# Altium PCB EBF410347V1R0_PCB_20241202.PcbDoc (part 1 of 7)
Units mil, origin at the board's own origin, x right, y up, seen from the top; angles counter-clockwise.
Board outline 5098.43 x 3464.57 mil, 6 copper layers (TOP, GND02, ART03, ART04, PWR05, BOTTOM), stack 47.2 mil thick; 566 components, 452 nets, 1905 pads, 1432 vias.
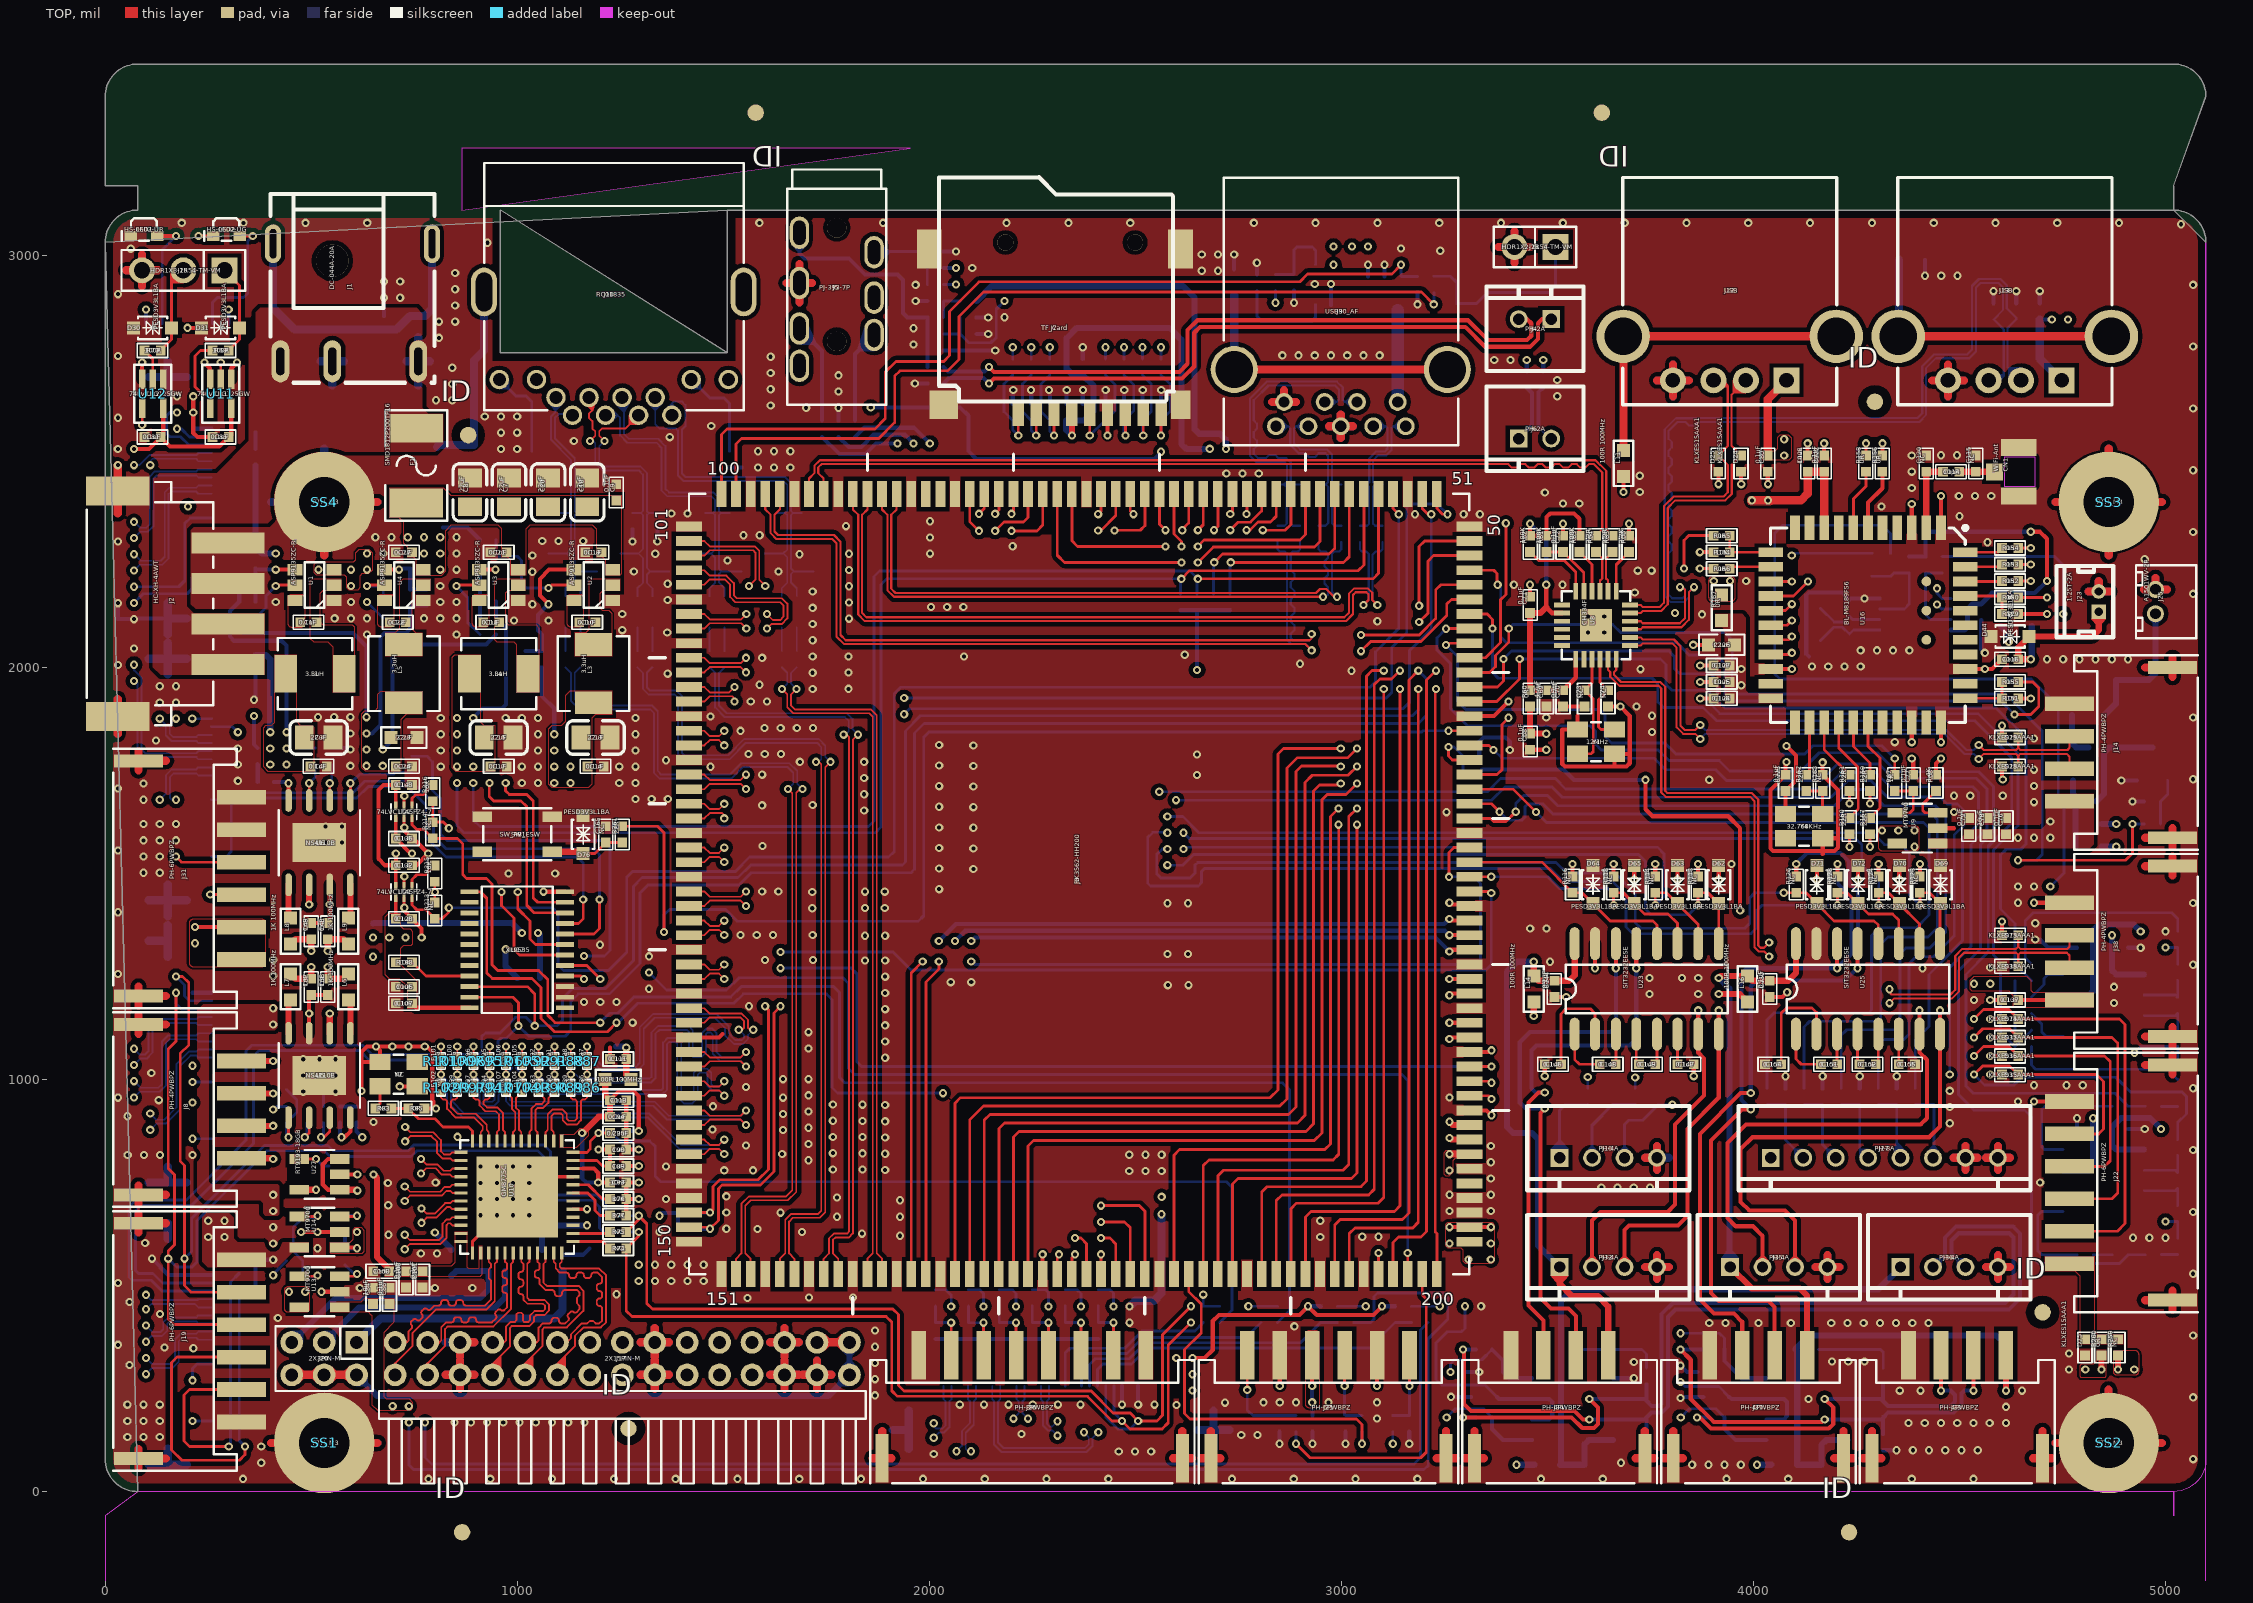
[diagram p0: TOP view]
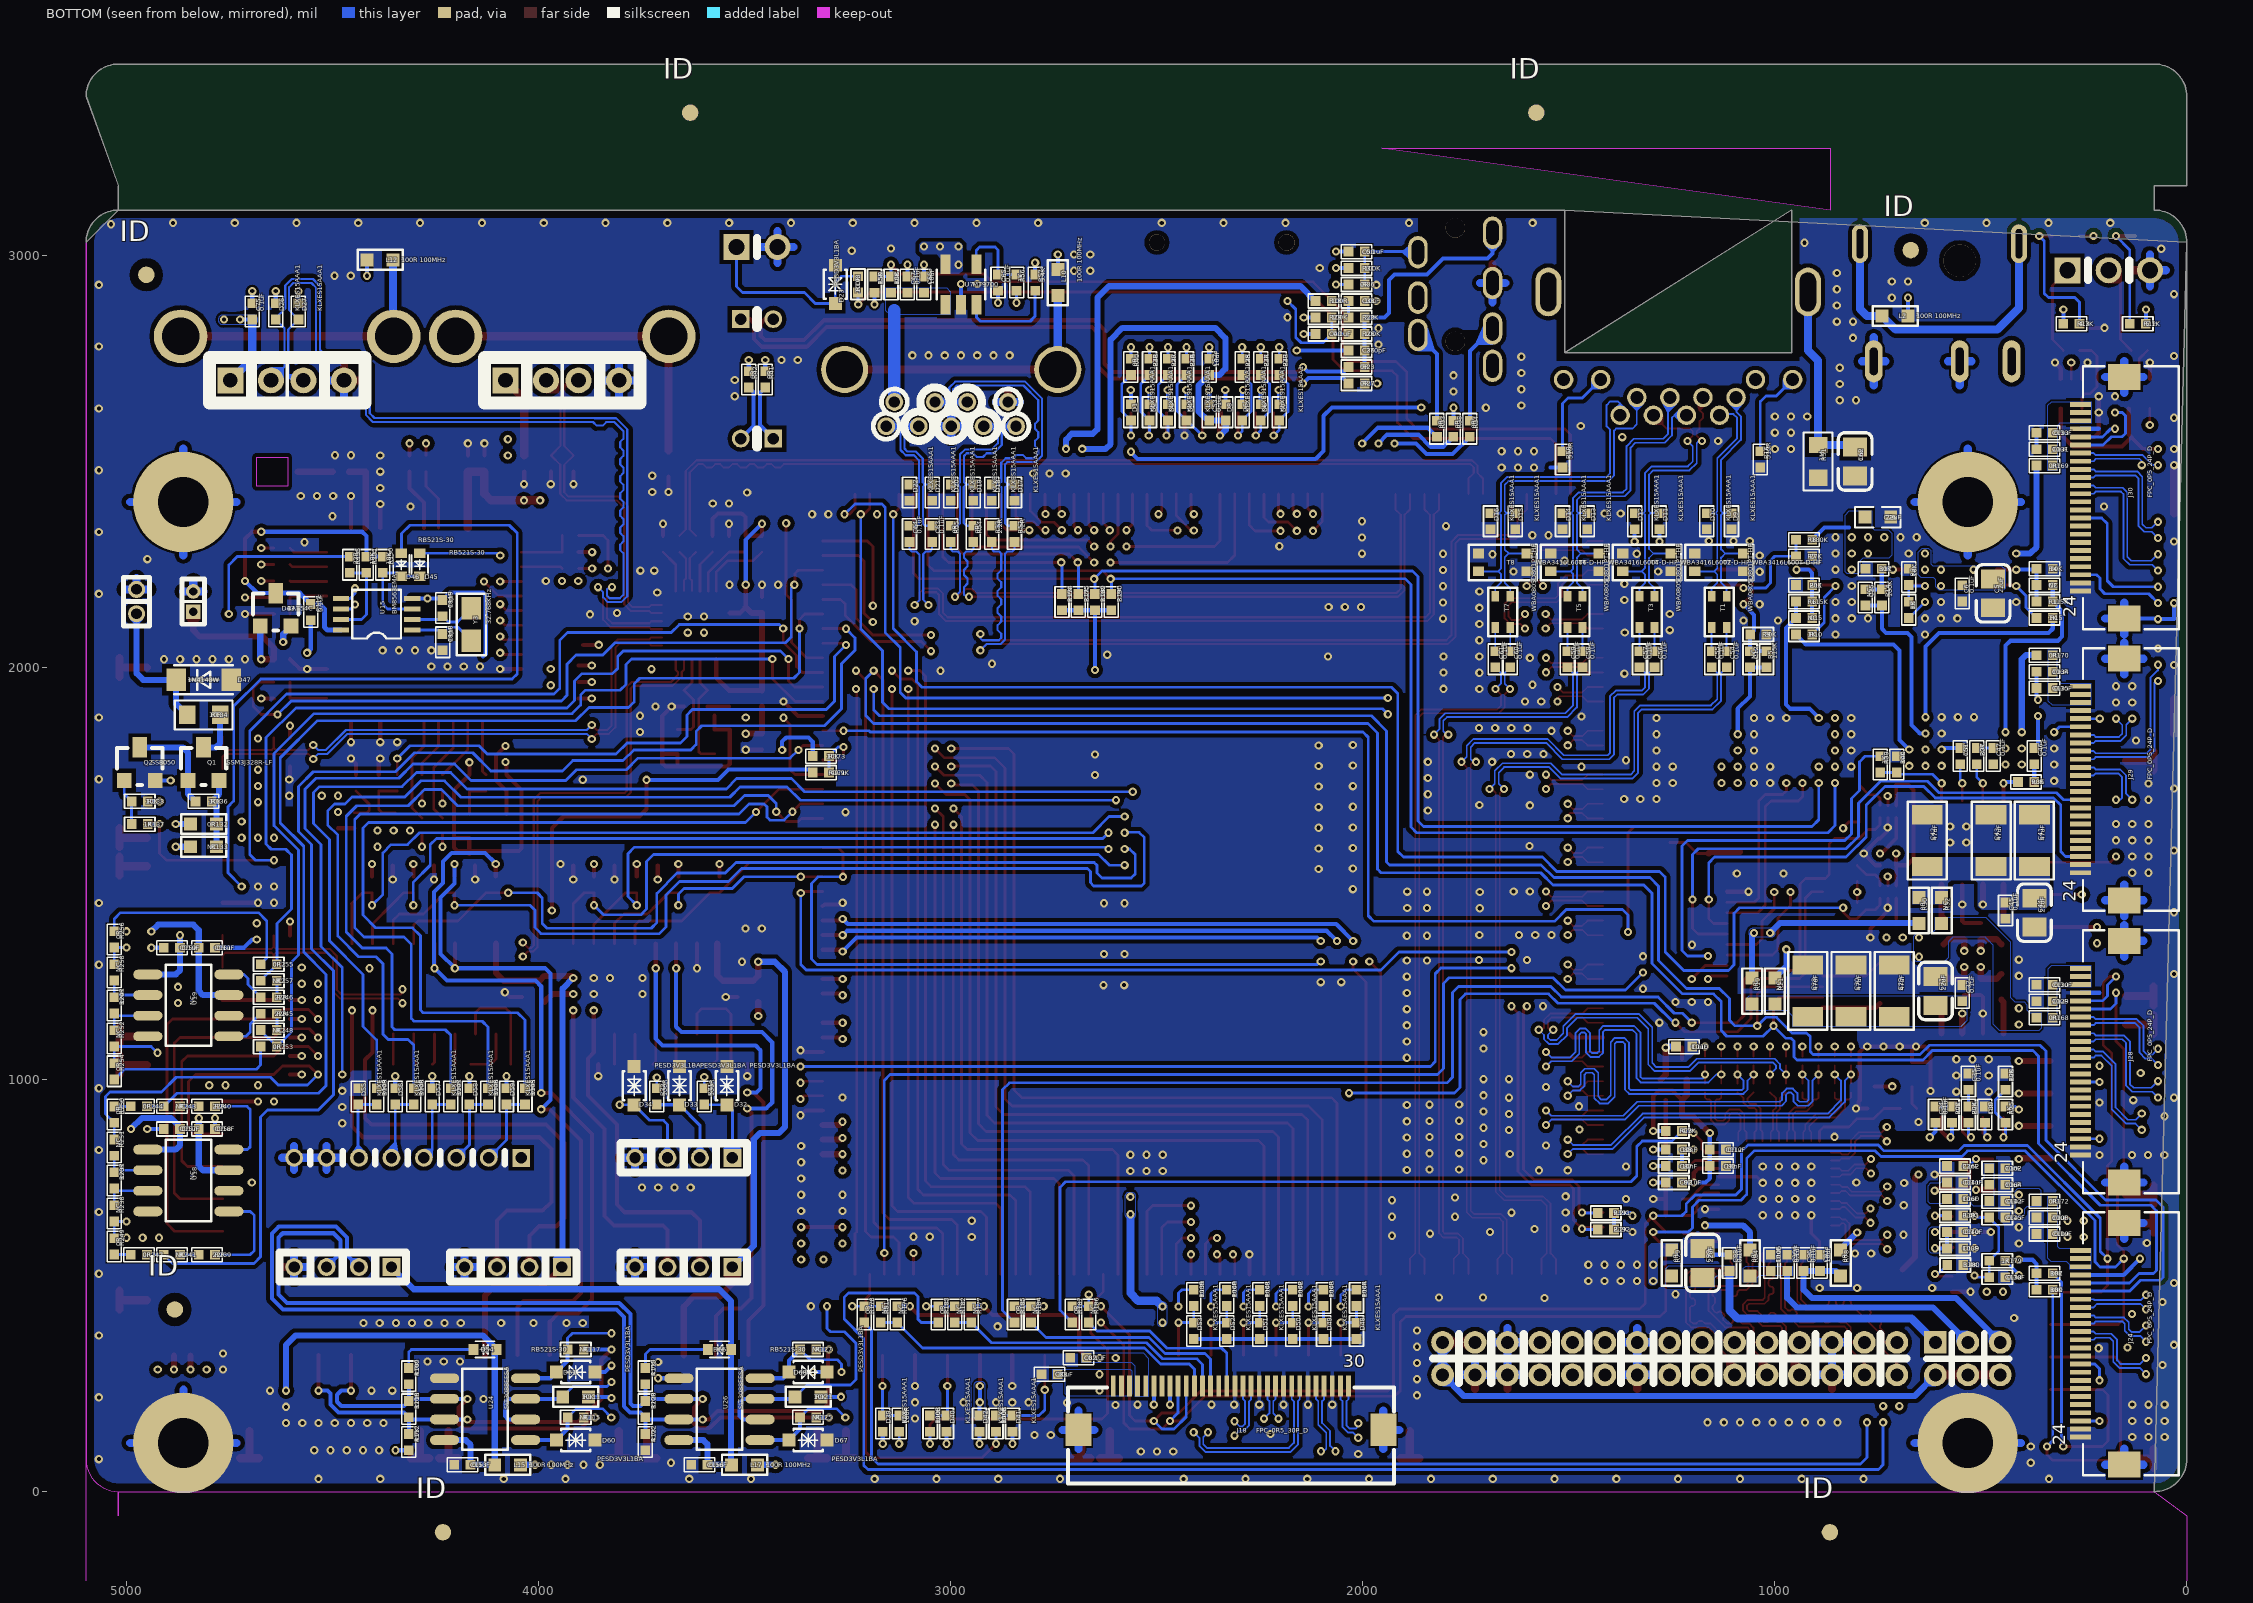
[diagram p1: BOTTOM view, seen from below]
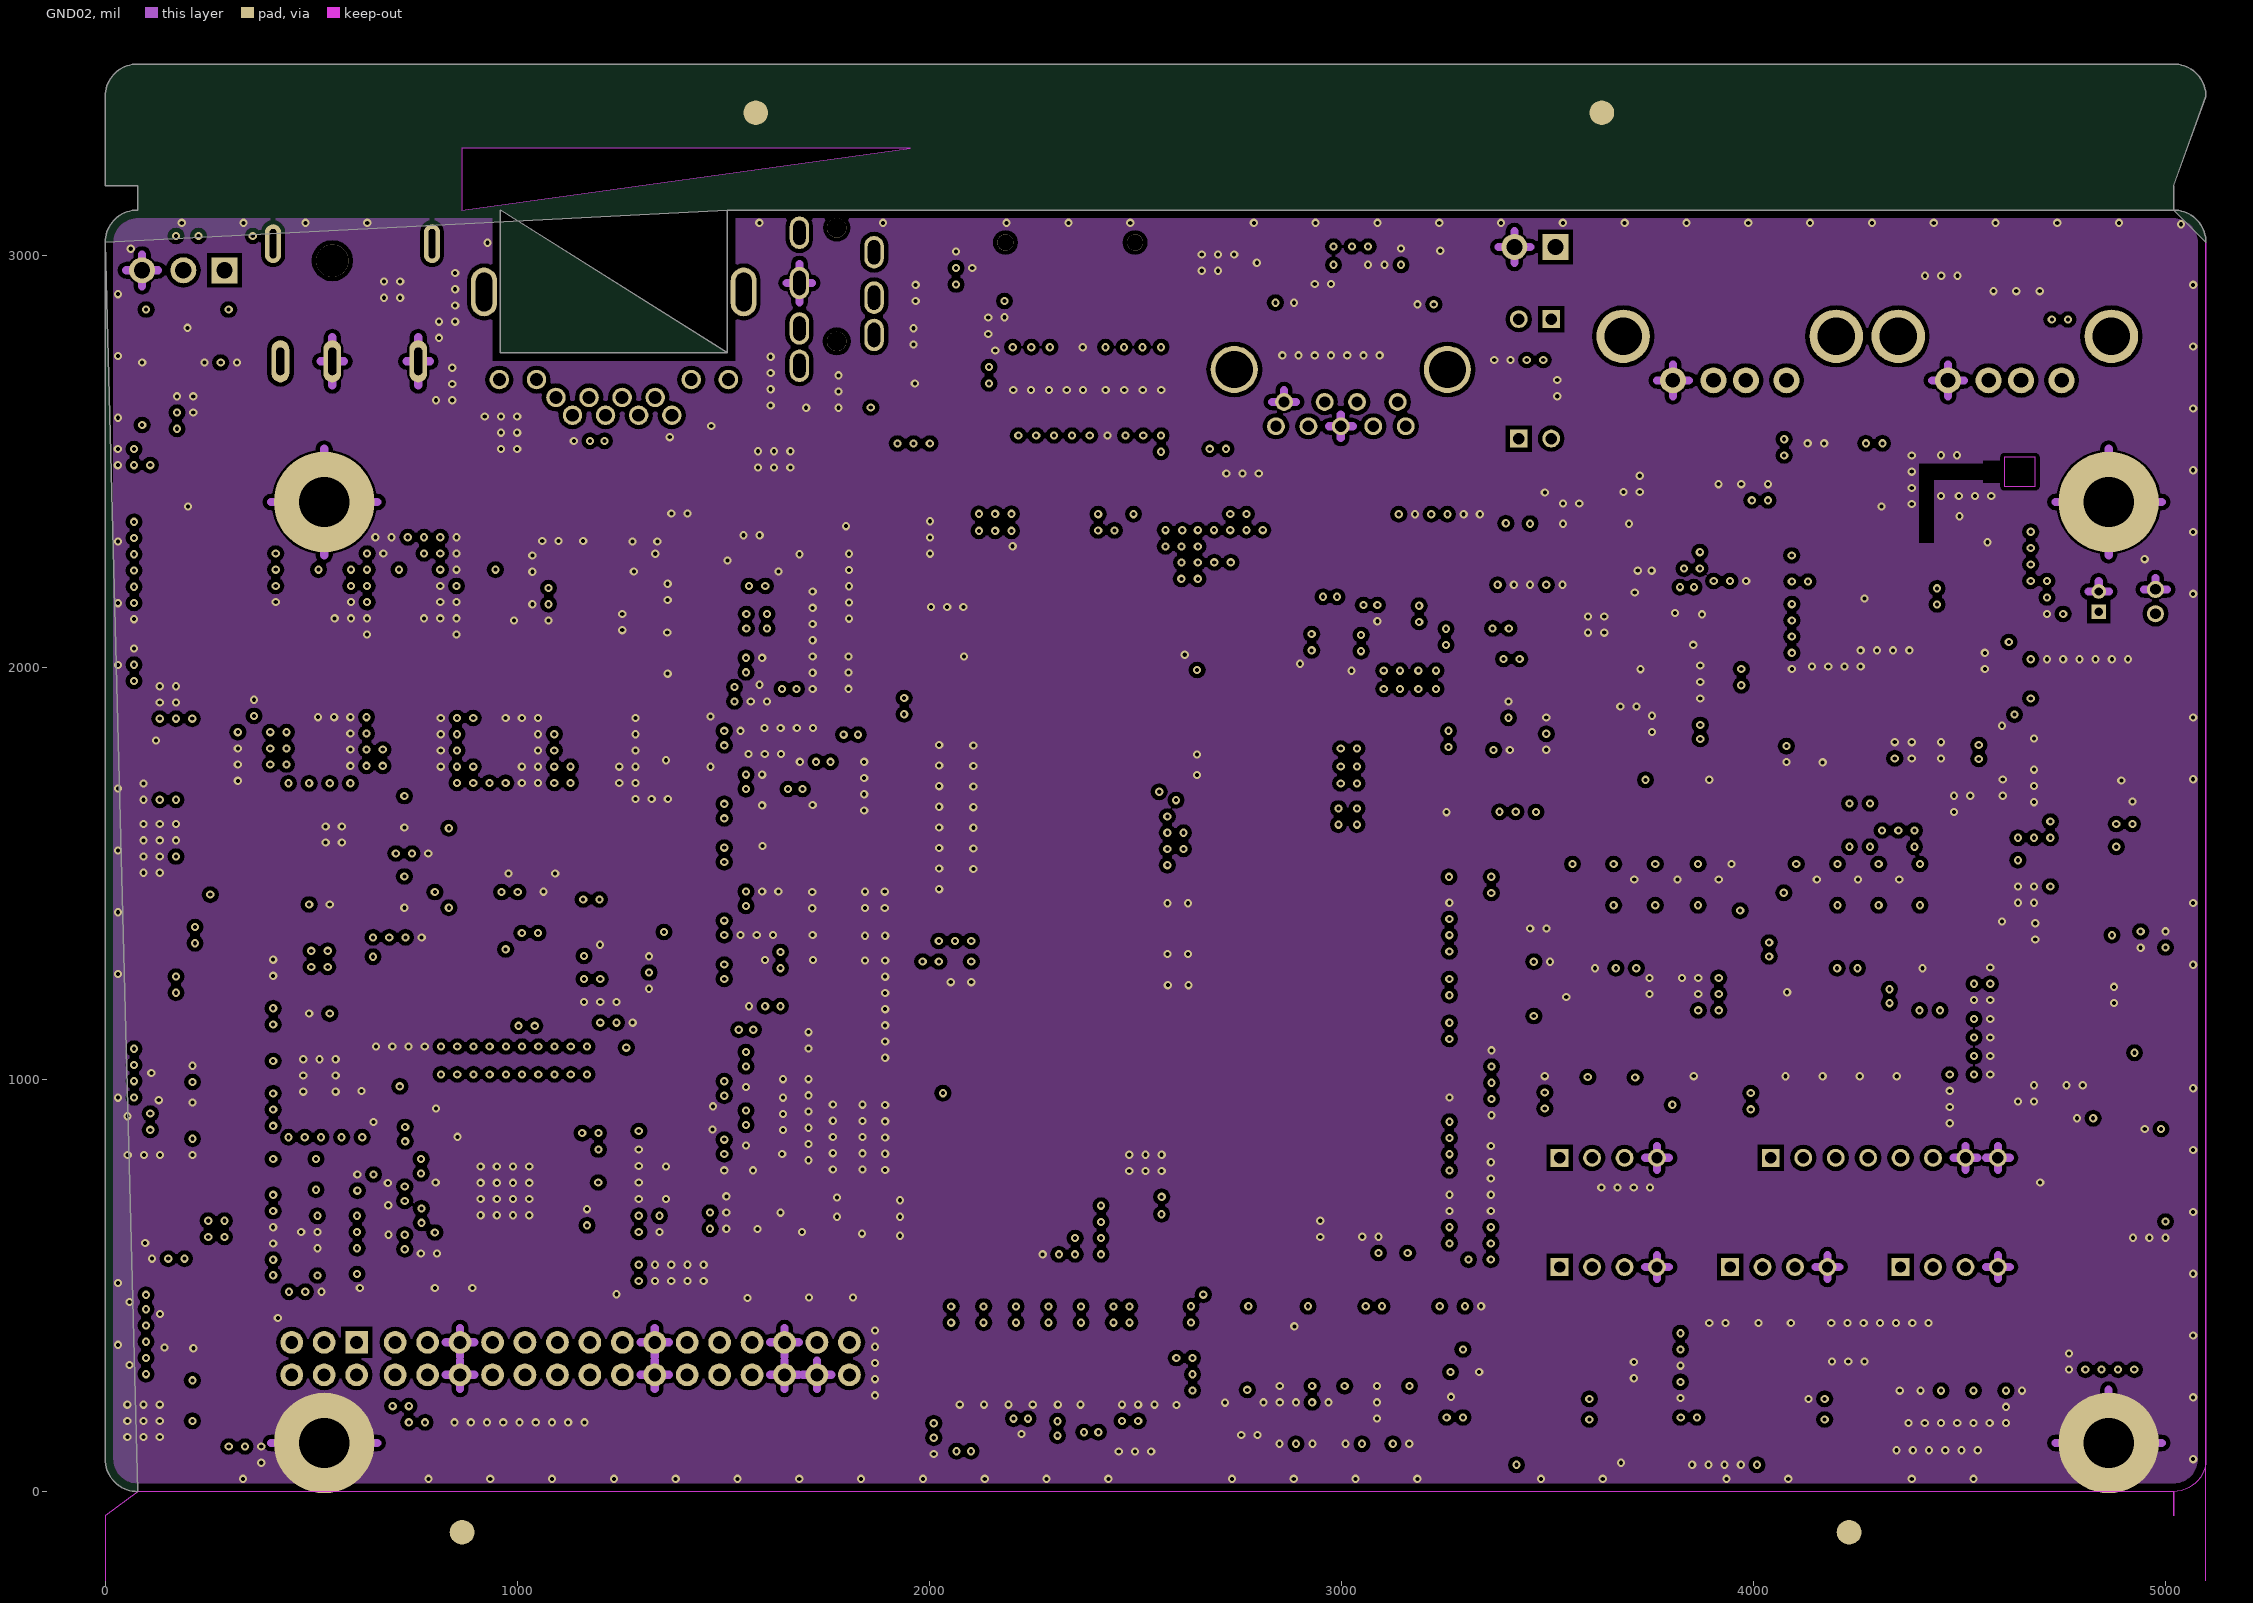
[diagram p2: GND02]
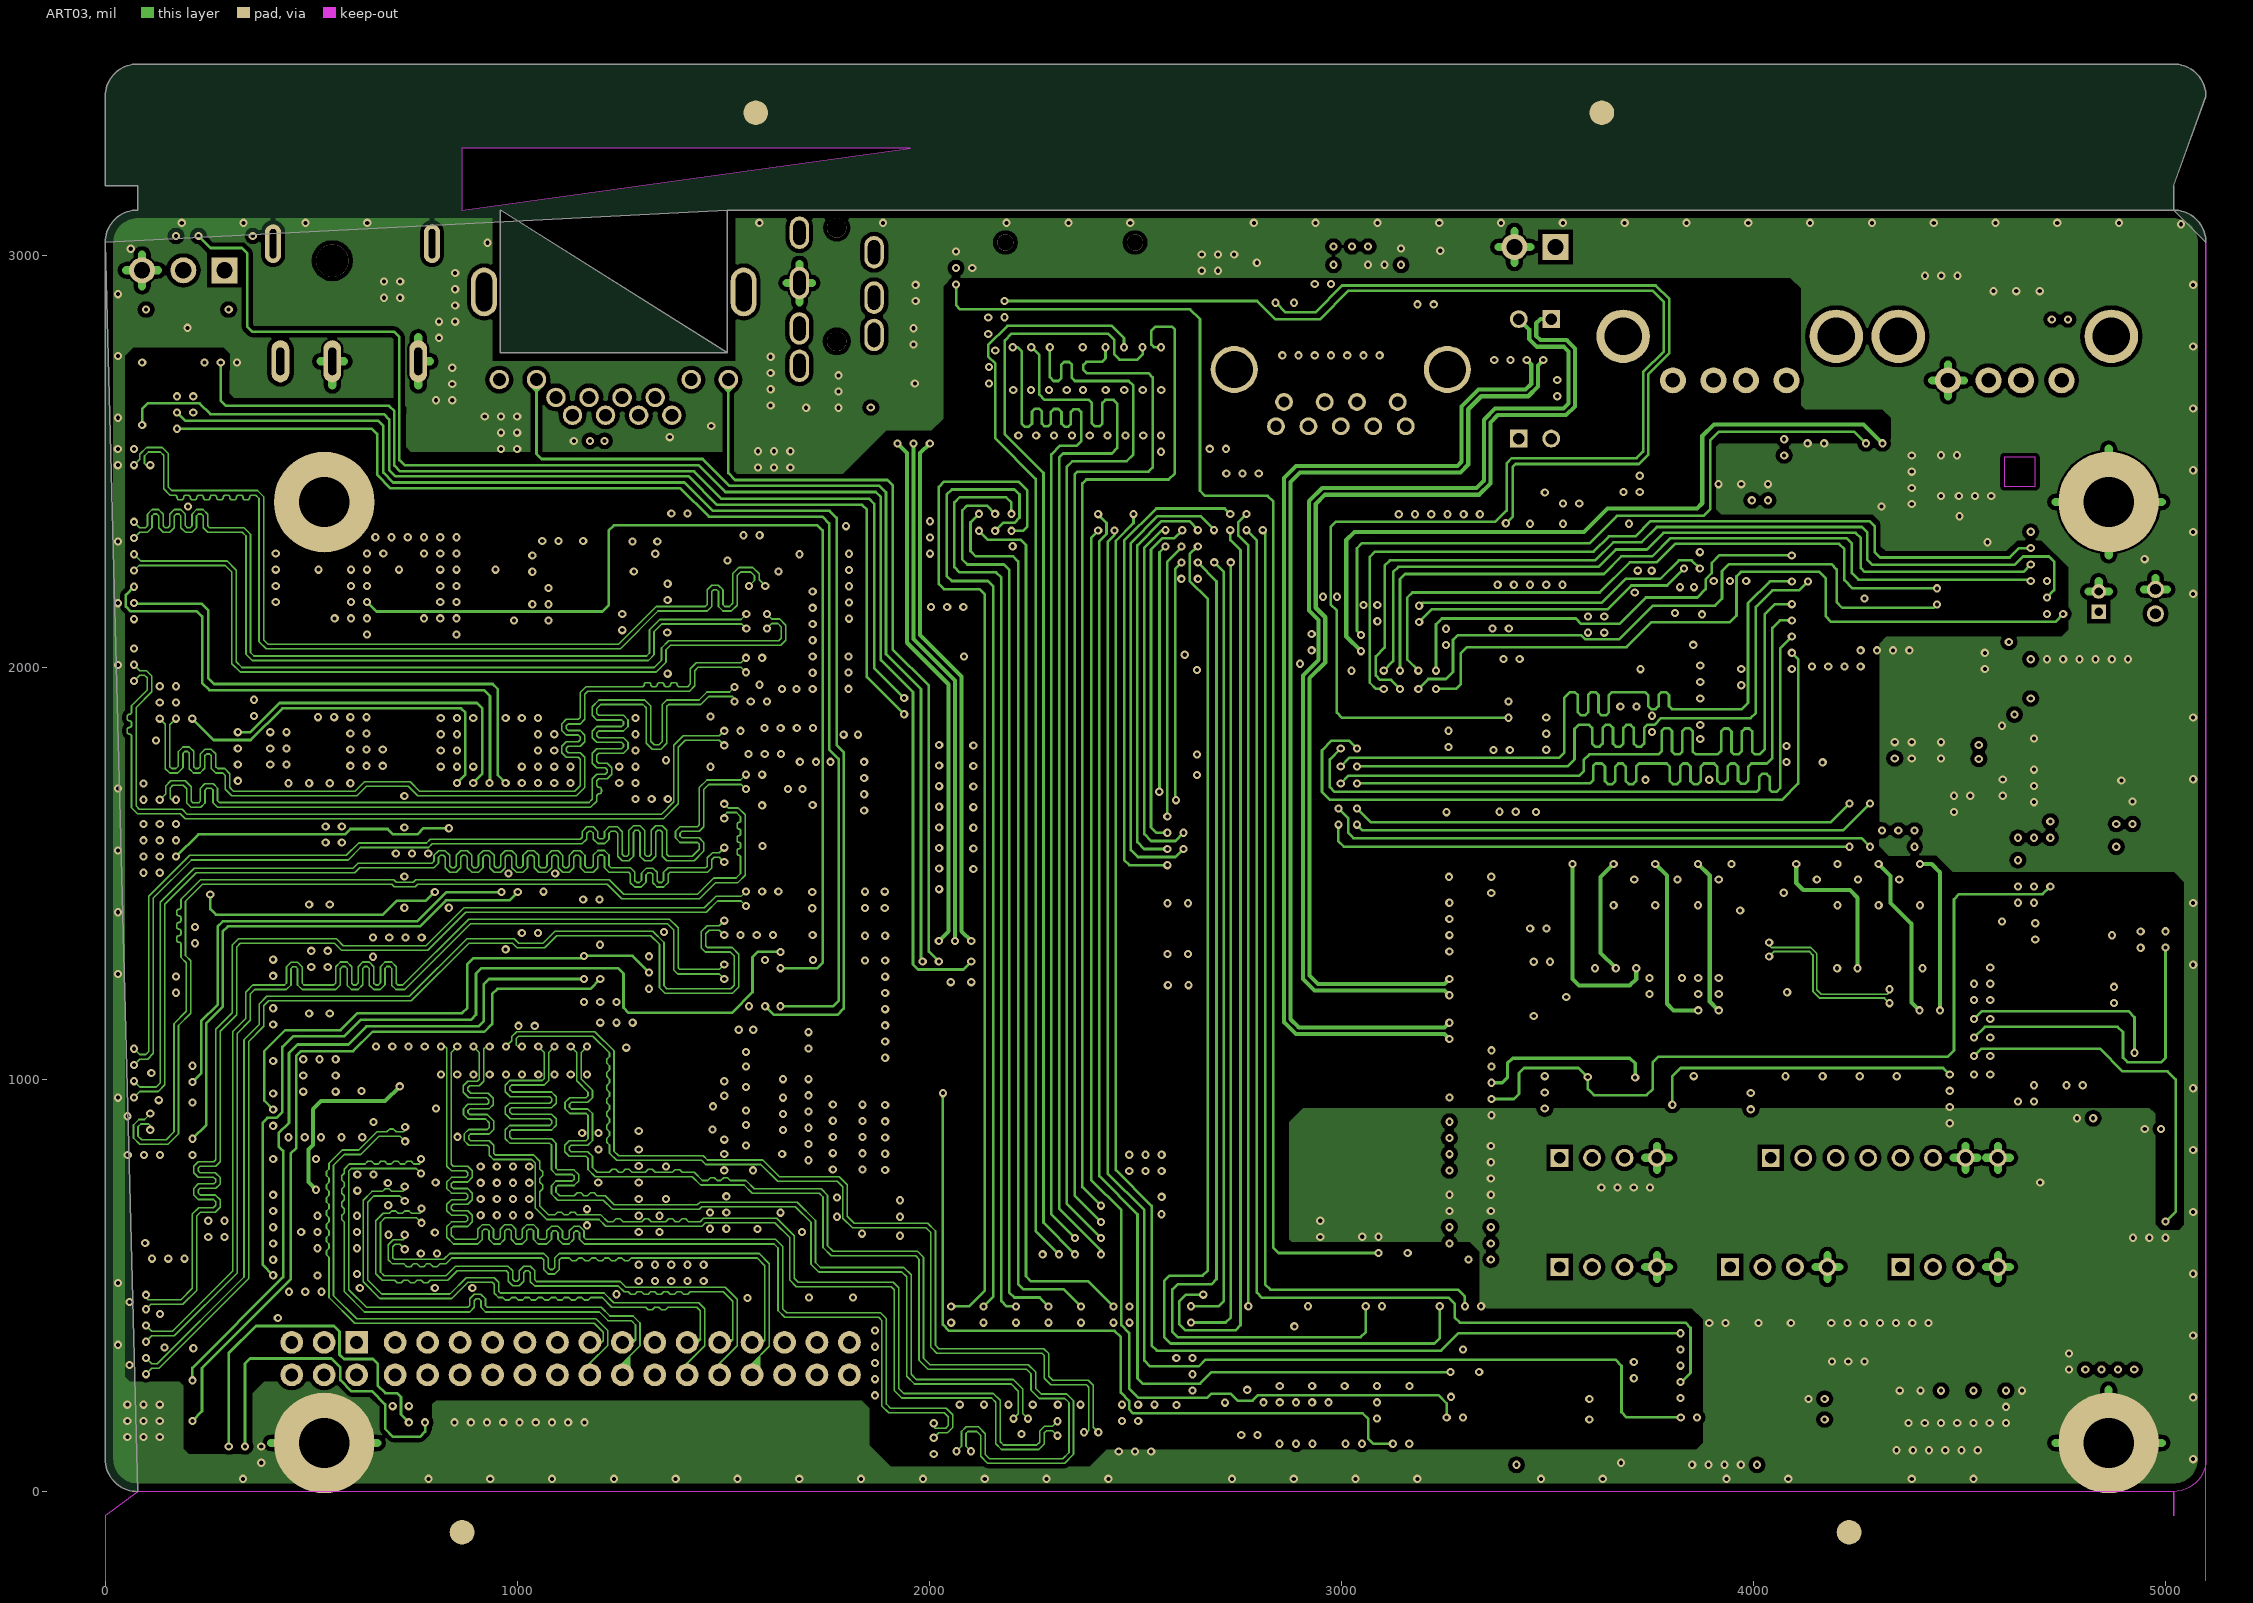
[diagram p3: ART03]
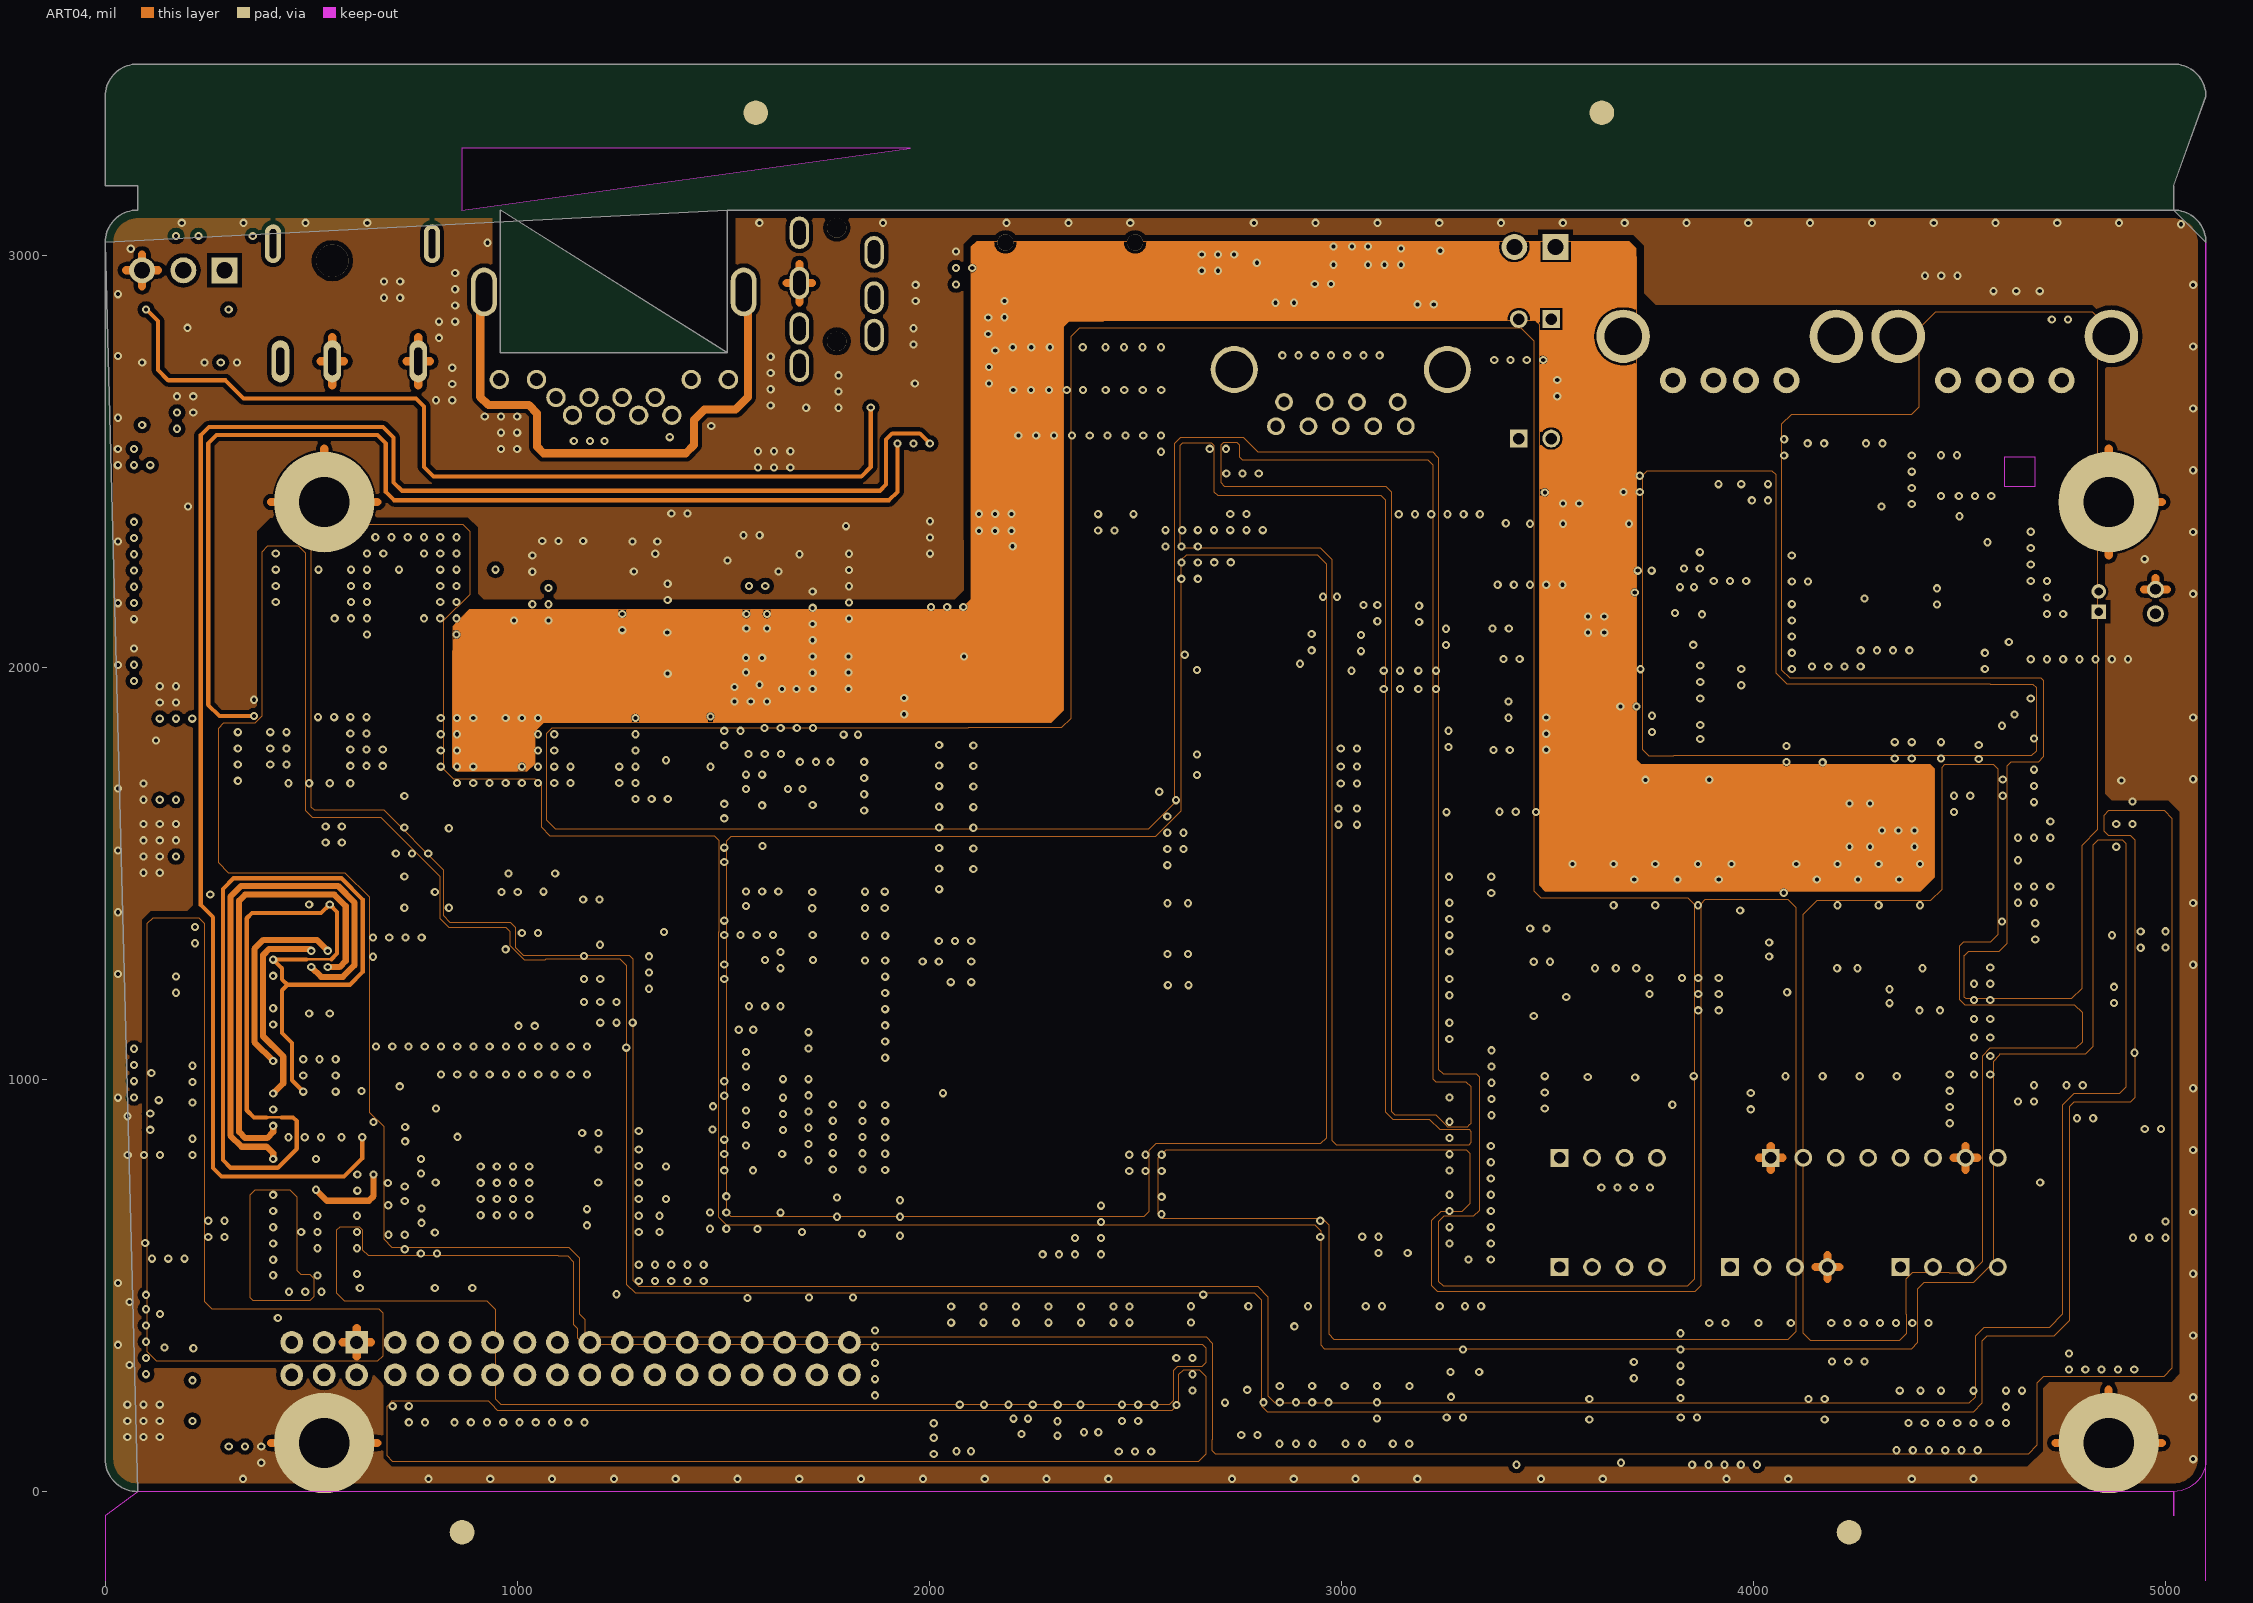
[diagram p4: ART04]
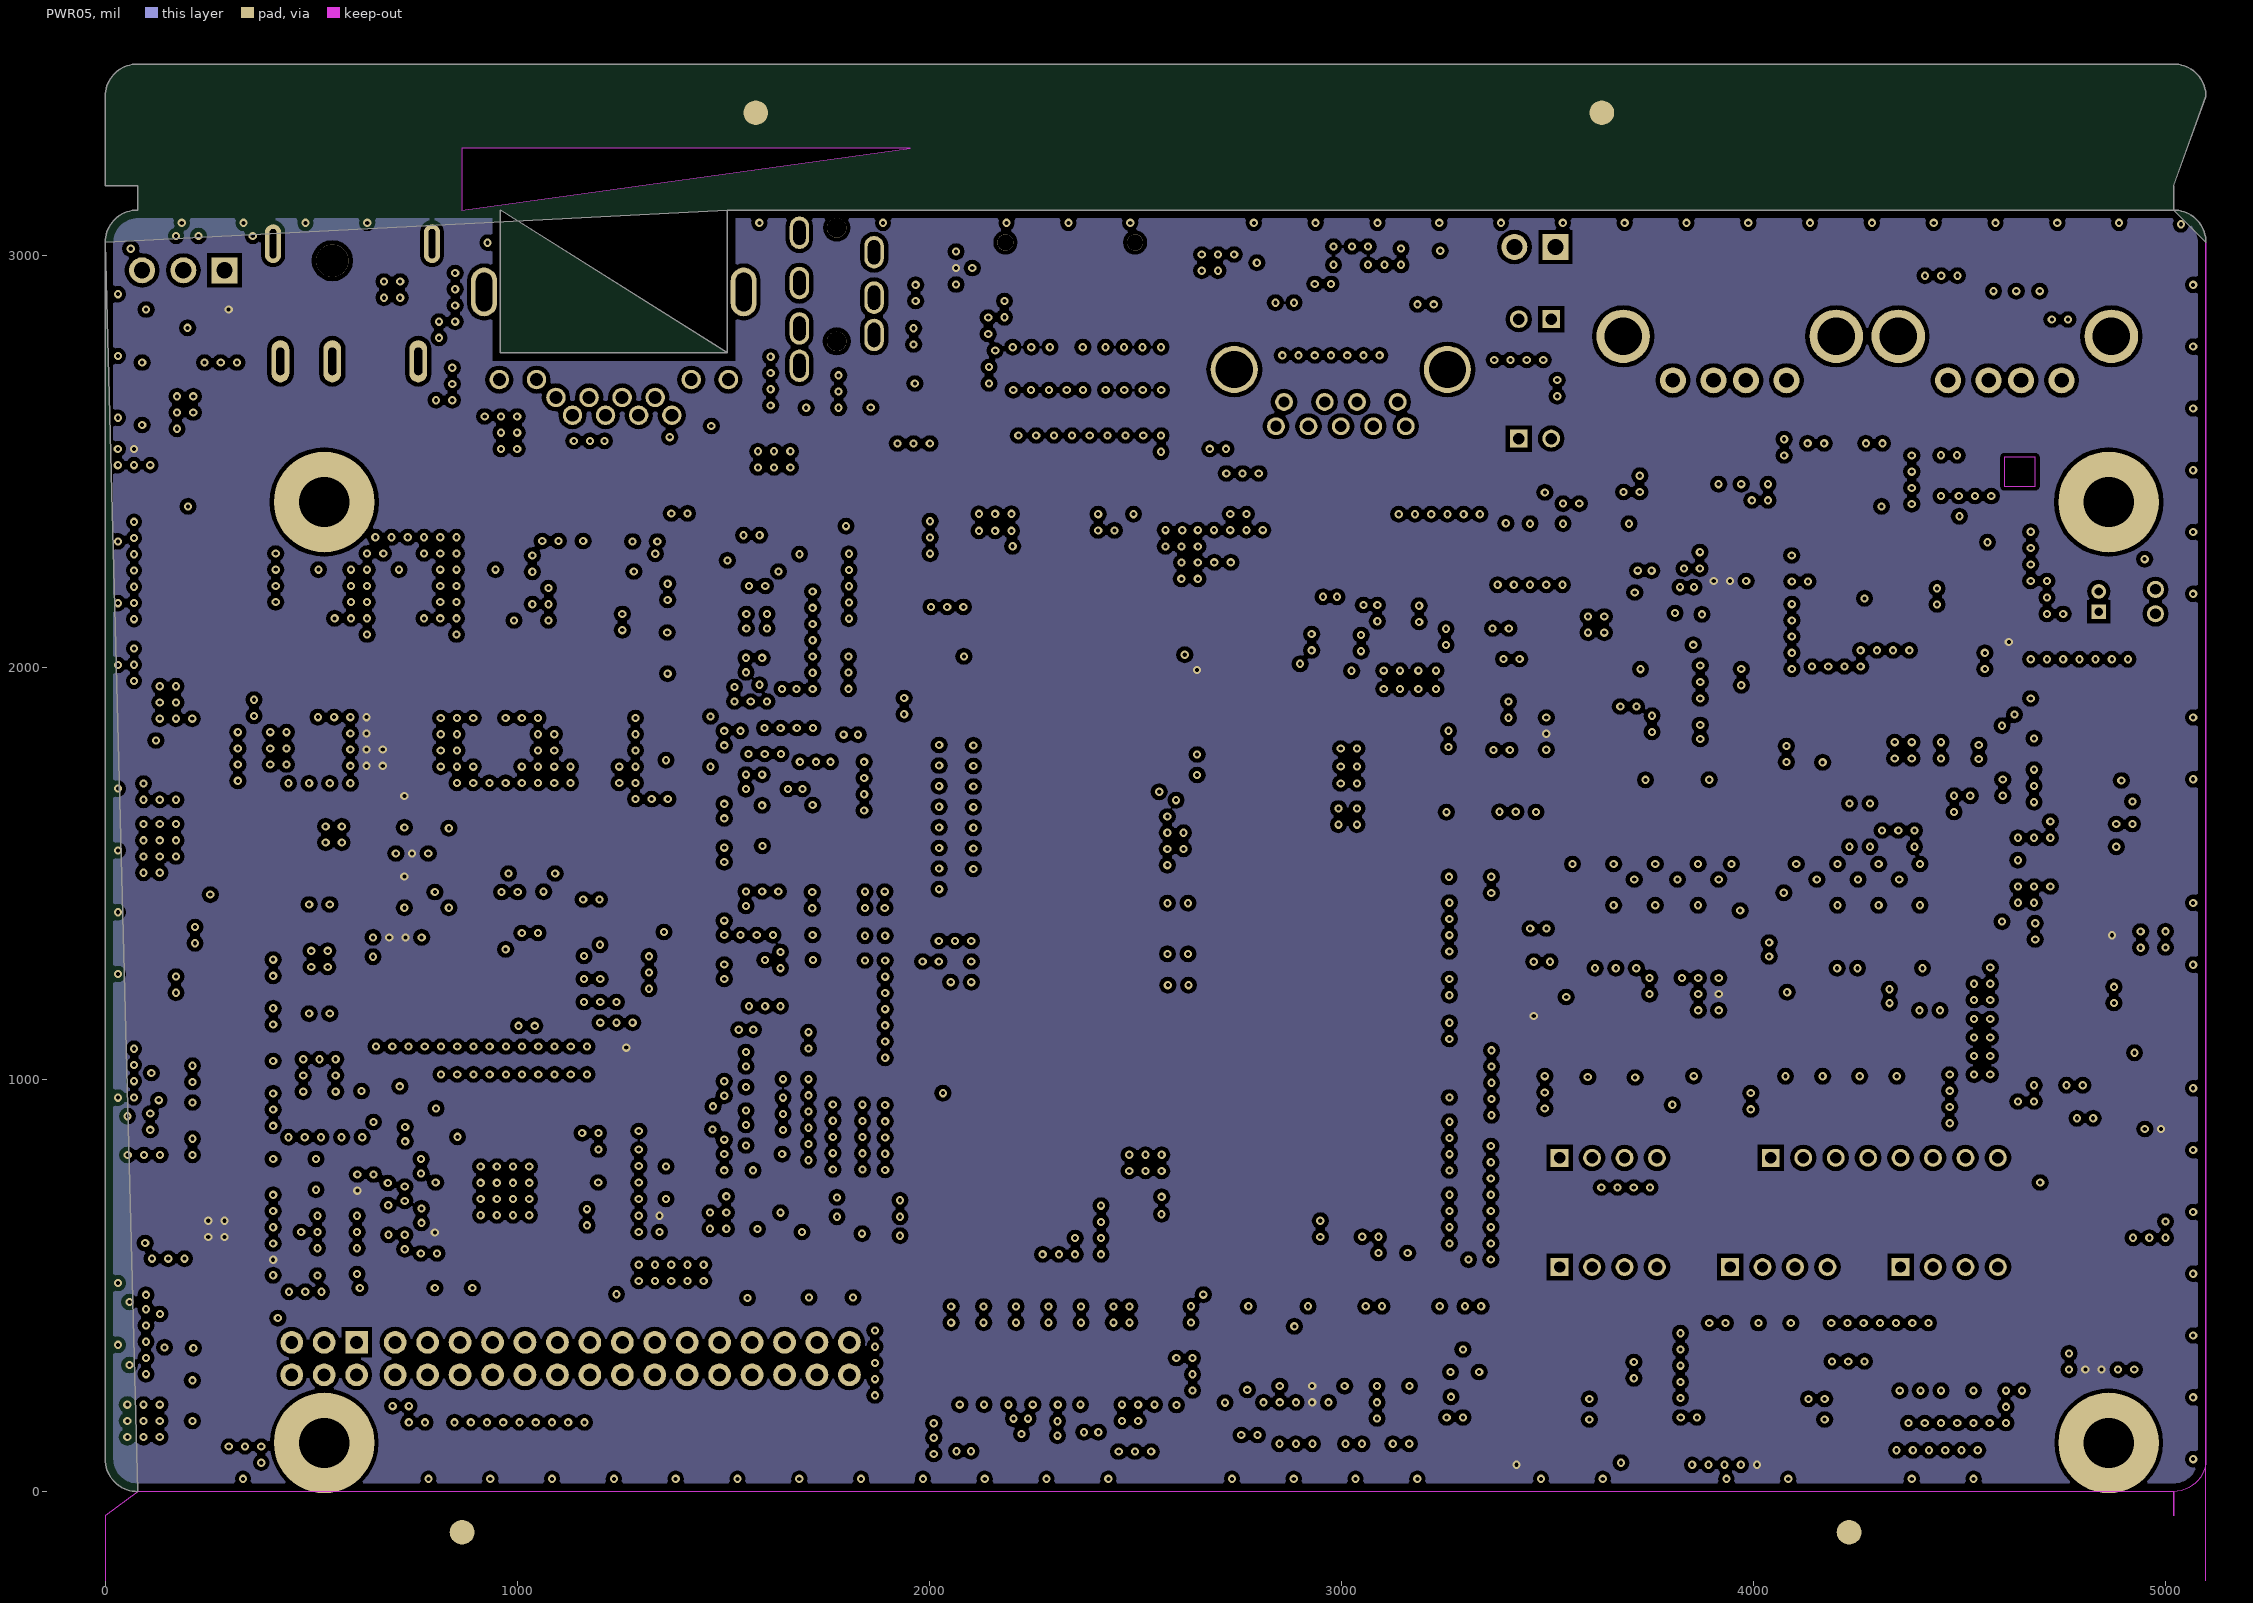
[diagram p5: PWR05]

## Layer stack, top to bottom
Top Solder: solder mask 0.4, Solder Resist, Dk 3.5
TOP: signal copper 1.2
Dielectric 1: core 8, FR-4, Dk 4.5
GND02: signal copper 1.2
Dielectric2: core 8, FR-4, Dk 4.5
ART03: signal copper 1.2
Dielectric3: core 8, FR-4, Dk 4.5
ART04: signal copper 1.2
Dielectric4: core 8, FR-4, Dk 4.5
PWR05: signal copper 1.2
Dielectric5: core 8, FR-4, Dk 4.5
BOTTOM: signal copper 1.2
Bottom Solder: solder mask 0.4, Solder Resist, Dk 3.5

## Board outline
1510.11,3110.24 1510.11,2763.78 958.93,3110.24 958.93,2763.78 1510.11,2763.78 1510.11,3110.24 5019.69,3110.24 cw(c5019.69,3031.5) 5019.69,3110.24 5019.69,3169.29 5098.43,3385.83 ccw(c5019.69,3385.83) 5019.69,3464.57 78.74,3464.57 ccw(c78.74,3385.83) 0,3385.83 0,3169.29 78.74,3169.29 78.74,3110.24 ccw(c78.74,3031.5) 0,78.74 ccw(c78.74,78.74) 0,3031.5
cut-out: 5098.43,3031.5 5098.43,78.74 cw(c5019.69,78.74) 5019.69,-59.05 5019.69,0 78.74,0 0,-59.05 0,-236.22 ccw(c78.74,-236.22) 5019.69,-314.96 ccw(c5019.69,-236.22) 5098.43,-236.22 5098.43,-59.05
cut-out: 1953.42,3260.24 865.62,3260.24 865.62,3110.24

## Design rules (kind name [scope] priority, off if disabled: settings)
Clearance [All] p1: gap=10 ignorepadtopadclearanceinfootprint=FALSE except(0: Arc-Hole Track-Hole SMDPad-Hole THPad-Hole Via-Hole Fill-Hole Poly-Hole Region-Hole Text-Hole)
DiffPairsRouting [All] p1: maxlimit=10 minlimit=10 mostfreqgap=10 toplayer_minwidth=15 toplayer_maxwidth=15 toplayer_prefwidth=15 midlayer1_minwidth=15 midlayer1_maxwidth=15 midlayer1_prefwidth=15 midlayer2_minwidth=15 midlayer2_maxwidth=15 midlayer2_prefwidth=15 midlayer3_minwidth=15 midlayer3_maxwidth=15 midlayer3_prefwidth=15 midlayer4_minwidth=15 midlayer4_maxwidth=15 midlayer4_prefwidth=15 bottomlayer_minwidth=15 bottomlayer_maxwidth=15 bottomlayer_prefwidth=15 maxuncoupledlength=500
PlaneConnect [All] p1: planeconnectstyle=Direct reliefexpansion=20 reliefentries=4 reliefconductorwidth=10 reliefairgap=10
PolygonConnect [All] p1: connectstyle=Direct reliefconductorwidth=10 reliefentries=4 polygonreliefangle="90 Angle" airgapwidth=10
RoutingVias [All] p1: holewidth=28 width=50 viastyle="Through Hole" minholewidth=28 minwidth=50 maxholewidth=28 maxwidth=50
SolderMaskExpansion [All] p1: expansion=4 istentingtop=FALSE
Width [All] p1: maxlimit=10 minlimit=10 preferedwidth=10 impedanceprofiledriven=TRUE minimp=0.660000 maximp=57.270000 favimp=0.460000
28 further rules are at their usual default settings.

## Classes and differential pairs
net class 50OHM: SDMMC0_CLK SDMMC0_CMD SDMMC0_D0 SDMMC0_D1 SDMMC0_D2 SDMMC0_D3 SDMMC0_DETN SDMMC1_CLK SDMMC1_CMD SDMMC1_D0 SDMMC1_D1 SDMMC1_D2 SDMMC1_D3
net class PWR: 12V 12V_IN GND LVDS_3V3 LVDS_5V LVDS_12V N17000237 RS232_1_3V3 RS232_2_3V3 RS485_1_3V3 RS485_2_3V3 USB30_OTG_VBUS USB_HUB_3V3 VCC3V3_SD VCC3V3_WIFI VCC5V0_SYS VCC5V0_USB VCC5V0_USB20_HUB VCC_LVDS VCC_RTC VCCA_1V8 VCCIO_ACODEC VDD_3V3 VDD_5V VDD_CAM0_5V VDD_CAM1_5V VDD_CAM2_5V VDD_CAM3_5V VDD_LCD_3V3 VDD_LCD_5V VDD_LVDS VDDIO_LVDS
differential pair USB30_OTG0_SSTX: +USB30_TXN -USB30_TXP
differential pair USB30_OTG0_SSRX: +USB30_RXN -USB30_RXP
differential pair USB30_OTG0_SSTX: +USB30_OTG0_SSTXP -USB30_TXN
differential pair USB30_OTG0_SSTX: +USB30_OTG0_SSTXN -USB30_OTG0_SSTXP
differential pair USB30_OTG0_SSRX: +USB30_OTG0_SSRXP -USB30_RXN
differential pair USB30_OTG0_SSRX: +USB30_OTG0_SSRXN -USB30_OTG0_SSRXP
differential pair USB3.0_D1: +USB30_OTG0_DM -USB30_OTG0_DP
differential pair USB3.0_D1: +USB30_DP -USB30_OTG0_DM
differential pair USB3.0_D1: +USB30_DM -USB30_DP
differential pair USB_HOST: +USB20_HOST1_DM -USB20_HOST1_DP
differential pair USB_HUB_D4: +USB_HUB_DM4 -USB_HUB_DP4
differential pair USB_HUB_D3: +USB_HUB_DM3 -USB_HUB_DP3
differential pair USB_HUB_D2: +USB_HUB_DM2 -USB_HUB_DP2
differential pair USB_HUB_D1: +USB_HUB_DM1 -USB_HUB_DP1
differential pair USB_HOST: +N16803237 -USB20_HOST1_DM
differential pair USB_HOST: +N16803235 -N16803237
differential pair ETH_M3: +N16788585 -N16788587
differential pair ETH_2: +N16788524 -N16788526
differential pair ETH_M1: +N16788463 -N16788475
differential pair ETH_M0: +N16788412 -N16788414
differential pair GM8775C_DA3: +MIPI_DSI_TX_D3N -MIPI_DSI_TX_D3P
differential pair GM8775C_DA2: +MIPI_DSI_TX_D2N -MIPI_DSI_TX_D2P
differential pair GM8775C_DA1: +MIPI_DSI_TX_D1N -MIPI_DSI_TX_D1P
differential pair GM8775C_DA0: +MIPI_DSI_TX_D0N -MIPI_DSI_TX_D0P
differential pair GM8775C_DAC: +MIPI_DSI_TX_CLKN -MIPI_DSI_TX_CLKP
differential pair GM8775C_DA3: +MIPI_DSI_D3P -MIPI_DSI_TX_D3N
differential pair GM8775C_DA3: +MIPI_DSI_D3N -MIPI_DSI_D3P
differential pair GM8775C_DA2: +MIPI_DSI_D2P -MIPI_DSI_TX_D2N
differential pair GM8775C_DA2: +MIPI_DSI_D2N -MIPI_DSI_D2P
differential pair GM8775C_DA1: +MIPI_DSI_D1P -MIPI_DSI_TX_D1N
differential pair GM8775C_DA1: +MIPI_DSI_D1N -MIPI_DSI_D1P
differential pair GM8775C_DA0: +MIPI_DSI_D0P -MIPI_DSI_TX_D0N
differential pair GM8775C_DA0: +MIPI_DSI_D0N -MIPI_DSI_D0P
differential pair GM8775C_DAC: +MIPI_DSI_CLKP -MIPI_DSI_TX_CLKN
differential pair GM8775C_DAC: +MIPI_DSI_CLKN -MIPI_DSI_CLKP
differential pair MIPI_CSI_RX1_D3: +MIPI_CSI_RX1_D3N -MIPI_CSI_RX1_D3P
differential pair MIPI_CSI_RX1_D2: +MIPI_CSI_RX1_D2N -MIPI_CSI_RX1_D2P
differential pair MIPI_CSI_RX1_D1: +MIPI_CSI_RX1_D1N -MIPI_CSI_RX1_D1P
differential pair MIPI_CSI_RX1_D0: +MIPI_CSI_RX1_D0N -MIPI_CSI_RX1_D0P
differential pair MIPI_CSI_RX1_CLK1: +MIPI_CSI_RX1_CLK1N -MIPI_CSI_RX1_CLK1P
differential pair MIPI_CSI_RX1_CLK0: +MIPI_CSI_RX1_CLK0N -MIPI_CSI_RX1_CLK0P
differential pair MIPI_CSI_RX0_D3: +MIPI_CSI_RX0_D3N -MIPI_CSI_RX0_D3P
differential pair MIPI_CSI_RX0_D2: +MIPI_CSI_RX0_D2N -MIPI_CSI_RX0_D2P
differential pair MIPI_CSI_RX0_D1: +MIPI_CSI_RX0_D1N -MIPI_CSI_RX0_D1P
differential pair MIPI_CSI_RX0_D0: +MIPI_CSI_RX0_D0N -MIPI_CSI_RX0_D0P
differential pair MIPI_CSI_RX0_CLK1: +MIPI_CSI_RX0_CLK1N -MIPI_CSI_RX0_CLK1P
differential pair MIPI_CSI_RX0_CLK0: +MIPI_CSI_RX0_CLK0N -MIPI_CSI_RX0_CLK0P
differential pair ETH_M3: +MDIP3_RJ45 -N16788585
differential pair ETH_2: +MDIP2_RJ45 -N16788524
differential pair ETH_M1: +MDIP1_RJ45 -N16788463
differential pair ETH_M0: +MDIP0_RJ45 -N16788412
differential pair ETH_M3: +MDIN3_RJ45 -MDIP3_RJ45
differential pair ETH_2: +MDIN2_RJ45 -MDIP2_RJ45
differential pair ETH_M1: +MDIN1_RJ45 -MDIP1_RJ45
differential pair ETH_M0: +MDIN0_RJ45 -MDIP0_RJ45
differential pair LVDS_TXB_D3: +LVDS_TXB_D3N -LVDS_TXB_D3P
differential pair LVDS_TXB_D2: +LVDS_TXB_D2N -LVDS_TXB_D2P
differential pair LVDS_TXB_D1: +LVDS_TXB_D1N -LVDS_TXB_D1P
differential pair LVDS_TXB_D0: +LVDS_TXB_D0N -LVDS_TXB_D0P
differential pair LVDS_TXB_CLK: +LVDS_TXB_CLKN -LVDS_TXB_CLKP
differential pair LVDS_TXA_D3: +LVDS_TXA_D3N -LVDS_TXA_D3P
differential pair LVDS_TXA_D2: +LVDS_TXA_D2N -LVDS_TXA_D2P
differential pair LVDS_TXA_D1: +LVDS_TXA_D1N -LVDS_TXA_D1P
differential pair LVDS_TXA_D0: +LVDS_TXA_D0N -LVDS_TXA_D0P
differential pair LVDS_TXA_CLK: +LVDS_TXA_CLKN -LVDS_TXA_CLKP
differential pair GM8775C_DAC: +GM8775C_DACP -MIPI_DSI_CLKN
differential pair GM8775C_DAC: +GM8775C_DACN -GM8775C_DACP
differential pair GM8775C_DA3: +GM8775C_DA3P -MIPI_DSI_D3N
differential pair GM8775C_DA3: +GM8775C_DA3N -GM8775C_DA3P
differential pair GM8775C_DA2: +GM8775C_DA2P -MIPI_DSI_D2N
differential pair GM8775C_DA2: +GM8775C_DA2N -GM8775C_DA2P
differential pair GM8775C_DA1: +GM8775C_DA1P -MIPI_DSI_D1N
differential pair GM8775C_DA1: +GM8775C_DA1N -GM8775C_DA1P
differential pair GM8775C_DA0: +GM8775C_DA0P -MIPI_DSI_D0N
differential pair GM8775C_DA0: +GM8775C_DA0N -GM8775C_DA0P
differential pair ETH_M3: +ETH_PHY_MDIP3 -MDIN3_RJ45
differential pair ETH_2: +ETH_PHY_MDIP2 -MDIN2_RJ45
differential pair ETH_M1: +ETH_PHY_MDIP1 -MDIN1_RJ45
differential pair ETH_M0: +ETH_PHY_MDIP0 -MDIN0_RJ45
differential pair ETH_M3: +ETH_PHY_MDIN3 -ETH_PHY_MDIP3
differential pair ETH_2: +ETH_PHY_MDIN2 -ETH_PHY_MDIP2
differential pair ETH_M1: +ETH_PHY_MDIN1 -ETH_PHY_MDIP1
differential pair ETH_M0: +ETH_PHY_MDIN0 -ETH_PHY_MDIP0

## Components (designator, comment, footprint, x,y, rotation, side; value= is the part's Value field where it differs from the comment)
C1 "CAP_NP_C0402_DISCRETE_0.1UF" C0402#1 493,2110 r0 top
C2 "CAP_NP_C0402_DISCRETE_NC" C0402#2 345,2200 r0 bottom
C3 "CAP_NP_C0805_DISCRETE_22UF" C0805 518,1830 r0 top
C4 "CAP_NP_C0402_DISCRETE_0.1UF" C0402#1 518,1760 r0 top
C5 "CAP_NP_C0805_DISCRETE_22UF" C0805 470,2180 r270 bottom
C6 "CAP_NP_C0402_DISCRETE_0.1UF" C0402#1 545,2180 r270 bottom
C7 "CAP_NP_C0805_DISCRETE_22UF" C0805 980,2425 r90 top
C8 "CAP_NP_C0805_DISCRETE_22UF" C0805 885,2425 r90 top
C9 "CAP_NP_C0402_DISCRETE_0.1UF" C0402#1 1240,2425 r90 top
C10 "CAP_NP_C0402_DISCRETE_0.1UF" C0402#1 1170,2110 r0 top
C11 "CAP_NP_C0402_DISCRETE_0.1UF" C0402#1 937,2110 r0 top
C12 "CAP_NP_C0402_DISCRETE_NC" C0402#1 1060,2020 r270 bottom
C13 "CAP_NP_C0805_DISCRETE_22UF" C0805 1190,1830 r0 top
C14 "CAP_NP_C0402_DISCRETE_0.1UF" C0402#1 1190,1760 r0 top
C15 "CAP_NP_C0402_DISCRETE_NC" C0402#1 929,2120 r0 bottom
C16 "CAP_NP_C0805_DISCRETE_22UF" C0805 955,1830 r0 top
C17 "CAP_NP_C0402_DISCRETE_0.1UF" C0402#1 955,1760 r0 top
C18 "CAP_NP_C0805_DISCRETE_22UF" C0805 1170,2425 r90 top
C19 "CAP_NP_C0402_DISCRETE_0.1UF" C0402#1 1185,2280 r180 top
C20 "CAP_NP_C0805_DISCRETE_22UF" C0805 1075,2425 r90 top
C21 "CAP_NP_C0402_DISCRETE_0.1UF" C0402#1 955,2280 r180 top
C22 "CAP_NP_C0402_DISCRETE_0.1UF" C0402#1 710,2110 r0 top
C23 "CAP_NP_C0603_DISCRETE_22UF" C0603#1 725,1830 r0 top
C24 "CAP_NP_C0402_DISCRETE_0.1UF" C0402#1 725,1760 r0 top
C25 "CAP_NP_C0402_DISCRETE_NC" C0402#1 780,2170 r270 bottom
C26 "CAP_NP_C0603_DISCRETE_22UF" C0603#2 750,2365 r0 bottom
C27 "CAP_NP_C0402_DISCRETE_0.1UF" C0402#1 725,2280 r180 top
C28 "CAP_NP_C1206_DISCRETE_47UF" C1206 920,1215 r90 bottom
C29 "CAP_NP_C1206_DISCRETE_47UF" C1206 710,1215 r90 bottom
C30 "CAP_NP_C1206_DISCRETE_47UF" C1206 815,1215 r90 bottom
C31 "CAP_NP_C0805_DISCRETE_22UF" C0805 610,1215 r90 bottom
C32 "CAP_NP_C0402_DISCRETE_0.1UF" C0402#1 545,1210 r90 bottom
C33 "CAP_NP_C0402_DISCRETE_10UF" C0402#2 2015,2889.37 r0 bottom
C34 "CAP_NP_C0402_DISCRETE_0.1UF" C0402#1 610,915 r90 bottom
C35 "CAP_NP_C0402_DISCRETE_0.1UF" C0402#1 530,995 r270 bottom
C36 "CAP_NP_C0402_DISCRETE_270PF" C0402#1 2015,2769.37 r0 bottom
C37 "CAP_NP_C0402_DISCRETE_1NF" C0402#1 500,1225 r270 top
C38 "CAP_NP_C0402_DISCRETE_1NF" C0402#1 540,1225 r270 top
C39 "CAP_NP_C0402_DISCRETE_1UF" C0402#1 490,915 r90 bottom
C40 "CAP_NP_C0402_DISCRETE_0.1UF" C0402#1 2095,2809.37 r0 bottom
C41 "CAP_NP_C1206_DISCRETE_47UF" C1206 370,1580 r90 bottom
C42 "CAP_NP_C1206_DISCRETE_47UF" C1206 630,1580 r90 bottom
C43 "CAP_NP_C1206_DISCRETE_47UF" C1206 475,1580 r90 bottom
C44 "CAP_NP_C0805_DISCRETE_22UF" C0805 370,1405 r270 bottom
C45 "CAP_NP_C0402_DISCRETE_0.1UF" C0402#1 440,1410 r270 bottom
C46 "CAP_NP_C0402_DISCRETE_0.1UF" C0402#1 370,1785 r270 bottom
C47 "CAP_NP_C0402_DISCRETE_0.1UF" C0402#1 470,1785 r90 bottom
C48 "CAP_NP_C0402_DISCRETE_1NF" C0402#1 540,1360 r90 top
C49 "CAP_NP_C0402_DISCRETE_1NF" C0402#1 500,1360 r90 top
C50 "CAP_NP_C0402_DISCRETE_0.1UF" C0402#1 2015,3009.37 r0 bottom
C51 "CAP_NP_C0402_DISCRETE_1UF" C0402#1 550,1785 r90 bottom
C52 "CAP_NP_C0402_DISCRETE_10UF" C0402#1 2372.61,2729.37 r90 bottom
C53 "CAP_NP_C0402_DISCRETE_0.1UF" C0402#1 2372.61,2619.37 r90 bottom
C54 "CAP_NP_C0402_DISCRETE_0.1UF" C0402#1 1116.79,2020 r90 bottom
C55 "CAP_NP_C0402_DISCRETE_0.1UF" C0402#1 1153.21,2020 r90 bottom
C56 "CAP_NP_C0402_DISCRETE_0.1UF" C0402#1 1291.79,2020 r90 bottom
C57 "CAP_NP_C0402_DISCRETE_0.1UF" C0402#1 1328.21,2020 r90 bottom
C58 "CAP_NP_C0402_DISCRETE_0.1UF" C0402#1 1466.79,2020 r90 bottom
C59 "CAP_NP_C0402_DISCRETE_0.1UF" C0402#1 1503.21,2020 r90 bottom
C60 "CAP_NP_C0402_DISCRETE_0.1UF" C0402#1 1641.79,2020 r90 bottom
C61 "CAP_NP_C0402_DISCRETE_0.1UF" C0402#1 1678.21,2020 r90 bottom
C62 "CAP_NP_C0805_DISCRETE_1NF" C0805 805,2500 r90 bottom
C63 "CAP_NP_C0402_DISCRETE_0.1UF" C0402#1 3045,2324.37 r270 bottom
C64 "CAP_NP_C0402_DISCRETE_0.1UF" C0402#1 3100,2324.37 r270 bottom
C65 "CAP_NP_C0402_DISCRETE_0.1UF" C0402#1 2885,2934.37 r270 bottom
C66 "CAP_NP_C0402_DISCRETE_10UF" C0402#1 3065,2929.37 r90 bottom
C67 "CAP_NP_C0402_DISCRETE_0.1UF" C0402#1 3105,2929.37 r90 bottom
C68 "CAP_NP_C0402_DISCRETE_0.1UF" C0402#1 3458.11,1820 r270 top
C69 "CAP_NP_C0402_DISCRETE_4.7UF" C0402#1 3498.11,1925 r270 top
C70 "CAP_NP_C0402_DISCRETE_0.1UF" C0402#1 3538.11,1925 r270 top
C71 "CAP_NP_C0402_DISCRETE_0.1UF" C0402#1 3458.11,2151.77 r90 top
C72 "CAP_NP_C0402_DISCRETE_0.1UF" C0402#1 3538.11,2300 r90 top
C73 "CAP_NP_C0402_DISCRETE_NC" C0402#1 3590.11,1925 r270 top
C74 "CAP_NP_C0402_DISCRETE_NC" C0402#1 3647.11,1925 r270 top
C75 "CAP_NP_C0402_DISCRETE_0.1UF" C0402#1 4695,2864.37 r90 bottom
C76 "CAP_NP_C0402_DISCRETE_0.1UF" C0402#1 4613.11,1615 r90 top
C77 "CAP_NP_C0402_DISCRETE_0.1UF" C0402#1 4388.11,1720 r90 top
C78 "CAP_NP_C0402_DISCRETE_10UF" C0402#1 4568.11,1615 r90 top
C79 "CAP_NP_C0402_DISCRETE_0.1UF" C0402#1 4523.11,1615 r90 top
C80 "CAP_NP_C0402_DISCRETE_0.1UF" C0402#1 4035,2495 r270 top
C81 "CAP_NP_C0402_DISCRETE_0.1UF" C0402#1 115,2559.37 r180 top
C82 "CAP_NP_C0402_DISCRETE_0.1UF" C0402#1 2690,325 r0 bottom
C83 "CAP_NP_C0402_DISCRETE_10UF" C0402#1 2760,285 r0 bottom
C84 "CAP_NP_C0402_DISCRETE_10UF" C0402#1 650,475 r90 top
C85 "CAP_NP_C0402_DISCRETE_0.1UF" C0402#1 280,2559.37 r180 top
C86 "CAP_NP_C0402_DISCRETE_0.1UF" C0402#1 690,475 r90 top
C87 "CAP_NP_C0402_DISCRETE_10NF" C0402#1 1245,790 r0 bottom
C88 "CAP_NP_C0402_DISCRETE_10NF" C0402#1 1245,830 r0 bottom
C89 "CAP_NP_C0402_DISCRETE_1UF" C0402#1 1245,790 r0 top
C90 "CAP_NP_C0402_DISCRETE_1UF" C0402#1 1245,830 r0 top
C91 "CAP_NP_C0402_DISCRETE_10NF" C0402#2 1138,790 r0 bottom
C92 "CAP_NP_C0402_DISCRETE_0.1UF" C0402#1 1245,750 r0 bottom
C93 "CAP_NP_C0402_DISCRETE_10NF" C0402#1 1245,750 r0 top
C94 "CAP_NP_C0402_DISCRETE_0.1UF" C0402#1 1245,910 r0 top
C95 "CAP_NP_C0402_DISCRETE_0.22UF" C0402#1 1245,870 r0 top
C96 "CAP_NP_C0402_DISCRETE_0.1UF" C0402#1 930,555 r90 bottom
C97 "CAP_NP_C0402_DISCRETE_10UF" C0402#1 890,555 r90 bottom
C98 "CAP_NP_C0402_DISCRETE_0.1UF" C0402#1 1110,555 r90 bottom
C99 "CAP_NP_C0805_DISCRETE_22UF" C0805 1175,555 r90 bottom
C100 "CAP_NP_C0402_DISCRETE_10NF" C0402#1 670,535 r180 top
C101 "CAP_NP_C0402_DISCRETE_0.1UF" C0402#1 770,515 r270 top
C102 "CAP_NP_C0402_DISCRETE_10NF" C0402#2 460,785 r0 bottom
C103 "CAP_NP_C0402_DISCRETE_0.1UF" C0402#1 730,515 r270 top
C104 "CAP_NP_C0402_DISCRETE_0.1UF" C0402#1 970,555 r90 bottom
C105 "CAP_NP_C0402_DISCRETE_10UF" C0402#1 1010,555 r90 bottom
C106 "CAP_NP_C0402_DISCRETE_10UF" C0402#1 725,1225 r180 top
C107 "CAP_NP_C0402_DISCRETE_0.1UF" C0402#1 725,1185 r180 top
C108 "CAP_NP_C0402_DISCRETE_10UF" C0402#1 345,665 r0 bottom
C109 "CAP_NP_C0402_DISCRETE_0.1UF" C0402#1 345,625 r0 bottom
C110 "CAP_NP_C0402_DISCRETE_10UF" C0402#2 1220,1080 r0 bottom
C111 "CAP_NP_C0402_DISCRETE_0.1UF" C0402#1 1245,1050 r180 top
C112 "CAP_NP_C0402_DISCRETE_0.1UF" C0402#2 1138,830 r0 bottom
C113 "CAP_NP_C0402_DISCRETE_10UF" C0402#1 1245,950 r0 top
C114 "CAP_NP_C0402_DISCRETE_10PF" C0402#1 4480,2475 r180 top
C115 "CAP_NP_C0402_DISCRETE_NC" C0402#1 4540,2495 r90 top
C116 "CAP_NP_C0402_DISCRETE_10UF" C0402#1 4623.11,2020 r180 top
C117 "CAP_NP_C0402_DISCRETE_0.1UF" C0402#1 4553.11,2134.37 r270 bottom
C118 "CAP_NP_C0402_DISCRETE_18PF" C0402#1 4233.11,2061.37 r270 bottom
C119 "CAP_NP_C0402_DISCRETE_18PF" C0402#1 4233.11,2144.37 r90 bottom
C120 "CAP_NP_C0402_DISCRETE_NC" C0402#1 4419.84,2494.96 r90 top
C121 "CAP_NP_C0402_DISCRETE_10UF" C0402#1 4131.81,2495 r90 top
C122 "CAP_NP_C0402_DISCRETE_0.1UF" C0402#1 4171.81,2495 r90 top
C123 "CAP_NP_C0402_DISCRETE_0.1UF" C0402#1 4078.11,1720 r90 top
C124 "CAP_NP_C0402_DISCRETE_0.1UF" C0402#1 3923.11,1925 r180 top
C125 "CAP_NP_C0402_DISCRETE_10UF" C0402#1 3923.11,1965 r180 top
C126 "CAP_NP_C0603_DISCRETE_22UF" C0603#1 3923.11,2055 r180 top
C127 "CAP_NP_C0402_DISCRETE_0.1UF" C0402#1 3923.11,2005 r180 top
C128 "CAP_NP_C0402_DISCRETE_0.1UF" C0402#1 725,1390 r0 top
C129 "CAP_NP_C0402_DISCRETE_10UF" C0402#1 345,1190 r0 bottom
C130 "CAP_NP_C0402_DISCRETE_0.1UF" C0402#1 345,1230 r0 bottom
C131 "CAP_NP_C0402_DISCRETE_10UF" C0402#1 345,2530 r0 bottom
C132 "CAP_NP_C0402_DISCRETE_0.1UF" C0402#1 725,1520 r0 top
C133 "CAP_NP_C0402_DISCRETE_0.1UF" C0402#1 345,2570 r0 bottom
C134 "CAP_NP_C0402_DISCRETE_10UF" C0402#1 345,1990 r0 bottom
C135 "CAP_NP_C0402_DISCRETE_0.1UF" C0402#1 345,1950 r0 bottom
C136 "CAP_NP_C0402_DISCRETE_0.1UF" C0402#1 725,1585 r0 top
C137 "CAP_NP_C0402_DISCRETE_0.1UF" C0402#1 4623.11,1192.99 r180 top
C138 "CAP_NP_C0402_DISCRETE_0.1UF" C0402#2 460,520 r0 bottom
C139 "CAP_NP_C0402_DISCRETE_10UF" C0402#2 562.5,590 r0 bottom
C140 "CAP_NP_C0402_DISCRETE_0.1UF" C0402#2 562.5,630 r0 bottom
C141 "CAP_NP_C0402_DISCRETE_0.1UF" C0402#2 562.5,750 r0 bottom
C142 "CAP_NP_C0402_DISCRETE_0.1UF" C0402#2 460,705 r0 bottom
C143 "CAP_NP_C0402_DISCRETE_0.1UF" C0402#1 725,1715 r0 top
C144 "CAP_NP_C0402_DISCRETE_0.1UF" C0402#1 3517.11,1220 r270 top
C145 "CAP_NP_C0402_DISCRETE_0.1UF" C0402#2 460,665 r0 bottom
C146 "CAP_NP_C0402_DISCRETE_0.1UF" C0402#1 3513.43,1037 r180 top
C147 "CAP_NP_C0402_DISCRETE_0.1UF" C0402#1 3835.59,1037 r0 top
C148 "CAP_NP_C0402_DISCRETE_0.1UF" C0402#1 3646.63,1037 r180 top
C149 "CAP_NP_C0402_DISCRETE_0.1UF" C0402#1 3742.11,1037 r180 top
C150 "CAP_NP_C0402_DISCRETE_0.1UF" C0402#1 4040,1220 r270 top
C151 "CAP_NP_C0402_DISCRETE_0.1UF" C0402#1 4183.63,1037 r180 top
C152 "CAP_NP_C0402_DISCRETE_0.1UF" C0402#1 4277.11,1037 r180 top
C153 "CAP_NP_C0402_DISCRETE_0.1UF" C0402#1 4185,65 r0 bottom
C154 "CAP_NP_C0402_DISCRETE_0.1UF" C0402#1 4048.11,1037 r180 top
C155 "CAP_NP_C0402_DISCRETE_0.1UF" C0402#1 4372.59,1037 r0 top
C156 "CAP_NP_C0402_DISCRETE_0.1UF" C0402#1 3610,65 r0 bottom
C157 "CAP_NP_C0402_DISCRETE_0.1UF" C0402#1 4890,880 r0 bottom
C158 "CAP_NP_C0402_DISCRETE_0.1UF" C0402#2 4805,880 r0 bottom
C159 "CAP_NP_C0402_DISCRETE_0.1UF" C0402#1 4890,1320 r0 bottom
C160 "CAP_NP_C0402_DISCRETE_10UF" C0402#2 562.5,710 r0 bottom
C161 "CAP_NP_C0402_DISCRETE_0.1UF" C0402#2 4805,1320 r0 bottom
C162 "CAP_NP_C0402_DISCRETE_22NF" C0402#1 562.5,790 r0 bottom
C164 "CAP_NP_C0402_DISCRETE_10UF" C0402#2 460,745 r0 bottom
C165 "CAP_NP_C0402_DISCRETE_NC" C0402#1 1215,1595 r90 top
CN1 "WIFI_ANT_UFL-3_WIFI-ANT" UFL-3 4626.1,2474.96 r270 top
D1 "DIODE BI-DIR TRIG_ES0402_KLXES1" ES0402 2562.61,2619.37 r90 bottom
D2 "DIODE BI-DIR TRIG_ES0402_KLXES1" ES0402 2517.61,2619.37 r90 bottom
D3 "DIODE BI-DIR TRIG_ES0402_KLXES1" ES0402 2472.61,2619.37 r90 bottom
D4 "DIODE BI-DIR TRIG_ES0402_KLXES1" ES0402 2427.61,2619.37 r90 bottom
D5 "DIODE BI-DIR TRIG_ES0402_KLXES1" ES0402 2292.61,2619.37 r90 bottom
D6 "DIODE BI-DIR TRIG_ES0402_KLXES1" ES0402 2247.61,2619.37 r90 bottom
D7 "DIODE BI-DIR TRIG_ES0402_KLXES1" ES0402 2202.61,2619.37 r90 bottom
D8 "DIODE BI-DIR TRIG_ES0402_KLXES1" ES0402 2332.61,2619.37 r90 bottom
D9 "DIODE BI-DIR TRIG_ES0402_KLXES1" ES0402 1105,2355 r90 bottom
D10 "DIODE BI-DIR TRIG_ES0402_KLXES1" ES0402 1165,2355 r90 bottom
D11 "DIODE BI-DIR TRIG_ES0402_KLXES1" ES0402 1280,2355 r90 bottom
D12 "DIODE BI-DIR TRIG_ES0402_KLXES1" ES0402 1340,2355 r90 bottom
D13 "DIODE BI-DIR TRIG_ES0402_KLXES1" ES0402 1455,2355 r90 bottom
D14 "DIODE BI-DIR TRIG_ES0402_KLXES1" ES0402 1515,2355 r90 bottom
D15 "DIODE BI-DIR TRIG_ES0402_KLXES1" ES0402 1630,2355 r90 bottom
D16 "DIODE BI-DIR TRIG_ES0402_KLXES1" ES0402 1690,2355 r90 bottom
D17 "DIODE BI-DIR TRIG_ES0402_KLXES1" ES0402 2845,2424.37 r270 bottom
D18 "DIODE BI-DIR TRIG_ES0402_KLXES1" ES0402 2900,2424.37 r270 bottom
D19 "DIODE BI-DIR TRIG_ES0402_KLXES1" ES0402 2945,2424.37 r270 bottom
D20 "DIODE BI-DIR TRIG_ES0402_KLXES1" ES0402 3000,2424.37 r270 bottom
D21 "DIODE BI-DIR TRIG_ES0402_KLXES1" ES0402 3045,2424.37 r270 bottom
D22 "DIODE BI-DIR TRIG_ES0402_KLXES1" ES0402 3100,2424.37 r270 bottom
D23 "DIODE BI-DIR TRIG_SOD323_T_PESD" SOD323_T#1 3280,2930 r90 bottom
D24 "DIODE BI-DIR TRIG_ES0402_KLXES1" ES0402 3970,2495 r270 top
D25 "DIODE BI-DIR TRIG_ES0402_KLXES1" ES0402 3915,2495 r270 top
D26 "DIODE BI-DIR TRIG_ES0402_KLXES1" ES0402 4638,2864.37 r90 bottom
D27 "DIODE BI-DIR TRIG_ES0402_KLXES1" ES0402 4583,2864.37 r90 bottom
D28 "DIODE BI-DIR TRIG_ES0402_KLXES1" ES0402 4623.11,1760 r180 top
D29 "DIODE BI-DIR TRIG_ES0402_KLXES1" ES0402 4623.11,1830 r180 top
D30 "DIODE BI-DIR TRIG_SOD323_T_PESD" SOD323_T#1 115,2824.37 r180 top
D31 "DIODE BI-DIR TRIG_SOD323_T_PESD" SOD323_T#1 280,2824.37 r180 top
D32 "DIODE BI-DIR TRIG_SOD323_T_PESD" SOD323_T#1 3543.11,984.99 r90 bottom
D33 "DIODE BI-DIR TRIG_SOD323_T_PESD" SOD323_T#1 3658.11,984.99 r90 bottom
D34 "DIODE BI-DIR TRIG_SOD323_T_PESD" SOD323_T#1 3768.11,984.99 r90 bottom
D35 "DIODE BI-DIR TRIG_ES0402_KLXES1" ES0402 4623.11,1012 r180 top
D36 "DIODE BI-DIR TRIG_ES0402_KLXES1" ES0402 4623.11,1057 r180 top
D37 "DIODE BI-DIR TRIG_ES0402_KLXES1" ES0402 4623.11,1102 r180 top
D38 "DIODE BI-DIR TRIG_ES0402_KLXES1" ES0402 4623.11,1275 r180 top
D39 "DIODE BI-DIR TRIG_ES0402_KLXES1" ES0402 3165,165 r270 bottom
D40 "DIODE BI-DIR TRIG_ES0402_KLXES1" ES0402 3010,165 r270 bottom
D41 "DIODE BI-DIR TRIG_ES0402_KLXES1" ES0402 2850,165 r270 bottom
D42 "DIODE BI-DIR TRIG_ES0402_KLXES1" ES0402 2930,165 r270 bottom
D43 "BAT54C_SOT23_BAT54C" SOT23 4638.11,2143.87 r0 bottom
D44 "DIODE BI-DIR TRIG_SOD323_T_PESD" SOD323_T#1 4623.11,2075 r0 top
D45 "DIODE_SCHTKY_SOD523_IC_RB521S-3" SOD523#1 4288.11,2249.37 r90 bottom
D46 "DIODE_SCHTKY_SOD523_IC_RB521S-3" SOD523#1 4333.11,2249.37 r90 bottom
D47 "DIODE_SOD-123_1N4148W" SOD-123 4813.11,1970 r0 bottom
D48 "DIODE BI-DIR TRIG_ES0402_KLXES1" ES0402 2015,390 r270 bottom
D49 "DIODE BI-DIR TRIG_ES0402_KLXES1" ES0402 2095,390 r270 bottom
D50 "DIODE BI-DIR TRIG_ES0402_KLXES1" ES0402 2170,390 r270 bottom
D51 "DIODE BI-DIR TRIG_ES0402_KLXES1" ES0402 2250,390 r270 bottom
D52 "DIODE BI-DIR TRIG_ES0402_KLXES1" ES0402 2330,390 r270 bottom
D53 "DIODE BI-DIR TRIG_ES0402_KLXES1" ES0402 2410,390 r270 bottom
D54 "DIODE_SCHTKY_SOD523_IC_RB521S-3" SOD523#2 4130,345 r0 bottom
D55 "DIODE BI-DIR TRIG_ES0402_KLXES1" ES0402 4438.11,959 r90 bottom
D56 "DIODE BI-DIR TRIG_ES0402_KLXES1" ES0402 4348.11,959 r90 bottom
D57 "DIODE BI-DIR TRIG_ES0402_KLXES1" ES0402 4258.11,959 r90 bottom
D58 "DIODE BI-DIR TRIG_ES0402_KLXES1" ES0402 4168.11,959 r90 bottom
D59 "DIODE BI-DIR TRIG_ES0402_KLXES1" ES0402 4078.11,959 r90 bottom
D60 "DIODE BI-DIR TRIG_SOD323_T_PESD" SOD323_T#2 3910,125 r0 bottom
D61 "DIODE BI-DIR TRIG_SOD323_T_PESD" SOD323_T#2 3910,290 r0 bottom
D62 "DIODE BI-DIR TRIG_SOD323_T_PESD" SOD323_T#1 3915.91,1473 r90 top
D63 "DIODE BI-DIR TRIG_SOD323_T_PESD" SOD323_T#1 3815.91,1473 r90 top
D64 "DIODE BI-DIR TRIG_SOD323_T_PESD" SOD323_T#1 3610.91,1473 r90 top
D65 "DIODE BI-DIR TRIG_SOD323_T_PESD" SOD323_T#1 3710.91,1473 r90 top
D66 "DIODE_SCHTKY_SOD523_IC_RB521S-3" SOD523#2 3561,345 r0 bottom
D67 "DIODE BI-DIR TRIG_SOD323_T_PESD" SOD323_T#2 3346,125 r0 bottom
D68 "DIODE BI-DIR TRIG_SOD323_T_PESD" SOD323_T#2 3346,290 r0 bottom
D69 "DIODE BI-DIR TRIG_SOD323_T_PESD" SOD323_T#1 4454.11,1473 r90 top
D70 "DIODE BI-DIR TRIG_SOD323_T_PESD" SOD323_T#1 4354.11,1473 r90 top
D71 "DIODE BI-DIR TRIG_SOD323_T_PESD" SOD323_T#1 4154.11,1473 r90 top
D72 "DIODE BI-DIR TRIG_SOD323_T_PESD" SOD323_T#1 4254.11,1473 r90 top
D73 "DIODE BI-DIR TRIG_ES0402_KLXES1" ES0402 4623.11,1350 r180 top
D74 "DIODE BI-DIR TRIG_ES0402_KLXES1" ES0402 4623.11,1147 r180 top
D75 "DIODE BI-DIR TRIG_ES0402_KLXES1" ES0402 4805,350 r270 top
D76 "DIODE BI-DIR TRIG_SOD323_T_PESD" SOD323_T#1 1160,1595 r90 top
F1 "FUSE_F1812_SMD1812P200TF16" F1812 755,2490 r270 top
J1 "DC-044A-20A_DC_IN_TH_3P_10R1X11" DC_IN_TH_3P_10R1X11R6 602.38,2917.36 r270 top
J2 "1X4PIN_SH_HC-XH-4AWT_HC-XH-4AWT" HC-XH-4AWT 170.05,2154.96 r270 top
J3 "RK3562-HH200_HH200-0R90-48R1X48" HH200-0R90-48R1X48R1-B 2363.74,1474.37 r90 top
J4 "1X2PIN_PH-1X2-2P0_L_PH-2A" PH-1X2-2P0_L 3470,2821.93 r180 top
J5 "PJ-393_AV7_6X14R50_TM_PJ-393-7P" AV7_6X14R50_TM 1775.43,2923.23 r0 top
J6 "1X2PIN_PH-1X2-2P0_L_PH-2A" PH-1X2-2P0_L 3470,2579.17 r0 top
J7 "TF_CARD_TFCARD_IO_TF_CARD" TFCARD 2304.73,2824.93 r180 top
J8 "1X4PIN_SH_PH2R0-A-1X4_PH-4PWBPZ" PH2R0-A-1X4 204.72,927.01 r90 top
J9 "USB30_AF_USB9-A-16R5X14R45-TM_U" USB9-A-16R5X14R45-TM 2998.85,2864.97 r180 top
J10 "RC01835_RJ8-15R2X16R2-TM-LED_RC" RJ8-15R2X16R2-TM-LED 1224.68,2905.51 r0 top
J11 "1X2PIN_HDR1X2-2R54-TM-VM_HDR1X2" HDR1X2-2R54-TM-VM 3470,3020.55 r180 top
J12 "USB CONN.-FEM-TYPEA-TH-RA_USB-A" USB-A-SM 3943.1,2914.85 r180 top
J13 "USB CONN.-FEM-TYPEA-TH-RA_USB-A" USB-A-SM 4610.74,2914.85 r180 top
J14 "1X4PIN_SH_PH2R0-A-1X4_PH-4PWBPZ" PH2R0-A-1X4 4893.39,1793.54 r270 top
J15 "1X3PIN_HDR1X3-2R54-TM-VM_HDR1X3" HDR1X3-2R54-TM-VM 189.81,2964.05 r180 top
J16 "1X4PIN_PH-1X4-2P0_PH-4A" PH-1X4-2P0 3647.95,833.62 r0 top
J17 "2X15PIN_HDR1X15-2-TM-RM_2X15PIN" HDR1X15-2-TM-RM 1255,322.83 r180 top
J18 "FPC-30P_FPC-30P-0P5_FPC_0R5_30P" FPC-30P-0P5 2320.01,148.33 r0 bottom
J19 "1X6PIN_SH_PH2R0-A-1X6_PH-6PWBPZ" PH2R0-A-1X6 204.72,363.86 r90 top
J20 "2X3PIN_HDR2X3-2R00-TM-VM_2X3PIN" HDR2X3-2R00-TM-VM 531.5,322.83 r180 top
J21 "1X6PIN_SH_PH2R0-A-1X6_PH-6PWBPZ" PH2R0-A-1X6 2970.63,205.12 r180 top
J22 "1X6PIN_SH_PH2R0-A-1X6_PH-6PWBPZ" PH2R0-A-1X6 4893.39,751.89 r270 top
J23 "1X2PIN_GH1P25_TH_2P_1.25T-2A" GH1P25_TH_2P 4804.69,2160 r90 top
J24 "FPC-24P_FPC_24P_0P5_FPC_0P5_24P" FPC_24P_0P5 151.57,358.58 r270 bottom
J25 "1X2PIN_ZH1P5MM_TH_2P_A1501WV-2P" ZH1P5MM_TH_2P 5001.5,2160 r90 top
J26 "1X8PIN_SH_PH2R0-A-1X8_PH-8PWBPZ" PH2R0-A-1X8 2250,205.12 r180 top
J27 "1X8PIN_PH-1X8-2P0_PH-8A" PH-1X8-2P0 4317.88,833.62 r0 top
J28 "FPC-24P_FPC_24P_0P5_FPC_0P5_24P" FPC_24P_0P5 151.57,1043.38 r270 bottom
J29 "FPC-24P_FPC_24P_0P5_FPC_0P5_24P" FPC_24P_0P5 151.57,1728.18 r270 bottom
J30 "FPC-24P_FPC_24P_0P5_FPC_0P5_24P" FPC_24P_0P5 151.57,2411.97 r270 bottom
J31 "1X6PIN_SH_PH2R0-A-1X6_PH-6PWBPZ" PH2R0-A-1X6 204.72,1486.22 r90 top
J32 "1X4PIN_PH-1X4-2P0_PH-4A" PH-1X4-2P0 3647.95,568.62 r0 top
J33 "1X4PIN_SH_PH2R0-A-1X4_PH-4PWBPZ" PH2R0-A-1X4 4494.72,205.12 r180 top
J34 "1X4PIN_SH_PH2R0-A-1X4_PH-4PWBPZ" PH2R0-A-1X4 3529.84,205.12 r180 top
J35 "1X4PIN_PH-1X4-2P0_PH-4A" PH-1X4-2P0 4061.65,568.62 r0 top
J36 "1X4PIN_PH-1X4-2P0_PH-4A" PH-1X4-2P0 4475.36,568.62 r0 top
J37 "1X4PIN_SH_PH2R0-A-1X4_PH-4PWBPZ" PH2R0-A-1X4 4012.28,205.12 r180 top
J38 "1X4PIN_SH_PH2R0-A-1X4_PH-4PWBPZ" PH2R0-A-1X4 4893.39,1311.1 r270 top
L1 "IND_L4520_DISCRETE_3.3UH" L4520 509,1984.9 r180 top
L2 "BEAD_L0603_DISCRETE_100R 100MHZ" L0603#1 708,2853 r0 bottom
L3 "IND_L4520_DISCRETE_3.3UH" L4520 1185,1984.9 r270 top
L4 "IND_L4520_DISCRETE_3.3UH" L4520 955,1984.9 r180 top
L5 "IND_L4520_DISCRETE_3.3UH" L4520 725,1984.9 r270 top
L6 "BEAD_L0603_DISCRETE_1K 100MHZ" L0603#2 590,1225 r90 top
L7 "BEAD_L0603_DISCRETE_1K 100MHZ" L0603#2 450,1225 r90 top
L8 "BEAD_L0603_DISCRETE_1K 100MHZ" L0603#2 450,1360 r270 top
L9 "BEAD_L0603_DISCRETE_1K 100MHZ" L0603#2 590,1360 r270 top
L10 "BEAD_L0603_DISCRETE_100R 100MHZ" L0603#2 2740,2934.37 r270 bottom
L11 "BEAD_L0603_DISCRETE_100R 100MHZ" L0603#2 3685,2495 r90 top
L12 "BEAD_L0603_DISCRETE_100R 100MHZ" L0603#1 4385,2989.37 r0 bottom
L13 "BEAD_L0603_DISCRETE_100R 100MHZ" L0603#2 1245,1000 r180 top
L14 "BEAD_L0603_DISCRETE_100R 100MHZ" L0603#2 3467.11,1220 r270 top
L15 "BEAD_L0603_DISCRETE_100R 100MHZ" L0603#2 4075,65 r0 bottom
L16 "BEAD_L0603_DISCRETE_100R 100MHZ" L0603#2 3986,1220 r270 top
L17 "BEAD_L0603_DISCRETE_100R 100MHZ" L0603#2 3500,65 r0 bottom
LED1 "LED_LED_HS_0602_UR_HS-0602-UR" LED_HS_0602_UR 94.09,3062.99 r0 top
LED2 "LED_LED_HS_0602_UR_HS-0602-UG" LED_HS_0602_UR 294.09,3062.99 r0 top
Q1 "MOSFET_P_SOT23_IC_SSM3J328R-LF" SOT23 4813.11,1769.5 r0 bottom
Q2 "NPN_SOT23_IC_SS8050" SOT23 4968.11,1769.5 r0 bottom
R1 "RES_R0402_DISCRETE_115K" R0402#1 345,2160 r0 bottom
R2 "RES_R0402_DISCRETE_10K" R0402#2 675,2220 r90 bottom
R3 "RES_R0402_DISCRETE_1K" R0402#2 675,2140 r270 bottom
R4 "RES_R0402_DISCRETE_20K" R0402#1 345,2240 r0 bottom
R5 "RES_R0402_DISCRETE_115K" R0402#2 1020,2020 r270 bottom
R6 "RES_R0402_DISCRETE_115K" R0402#2 929,2160 r0 bottom
R7 "RES_R0402_DISCRETE_27K" R0402#1 929,2270 r0 bottom
R8 "RES_R0402_DISCRETE_180K" R0402#1 929,2310 r0 bottom
R9 "RES_R0402_DISCRETE_20K" R0402#1 1040,2080 r0 bottom
R10 "RES_R0402_DISCRETE_1K" R0402#2 929,2080 r0 bottom
R11 "RES_R0402_DISCRETE_20K" R0402#2 929,2200 r0 bottom
R12 "RES_R0402_DISCRETE_5.1K" R0402#2 119,2834.37 r0 bottom
R13 "RES_R0402_DISCRETE_4.7K" R0402#1 280,2834.37 r0 bottom
R14 "RES_R0402_DISCRETE_100K" R0402#2 740,2170 r270 bottom
R15 "RES_R0402_DISCRETE_1K" R0402#1 345,2120 r0 bottom
R16 "RES_R0402_DISCRETE_510R" R0402#2 1035,2505 r270 bottom
R17 "RES_R0402_DISCRETE_30K" R0402#2 760,2240 r0 bottom
R18 "RES_R0402_DISCRETE_100R" R0402#2 2095,2889.37 r0 bottom
R19 "RES_R0603_DISCRETE_0R" R0603#1 1055,1215 r270 bottom
R20 "RES_R0402_DISCRETE_2.2K" R0402#1 2015,2849.37 r0 bottom
R21 "RES_R0603_DISCRETE_NC" R0603#1 1000,1215 r270 bottom
R22 "RES_R0402_DISCRETE_20K" R0402#2 570,915 r270 bottom
R23 "RES_R0402_DISCRETE_0R" R0402#2 2015,2729.37 r0 bottom
R24 "RES_R0402_DISCRETE_20K" R0402#2 530,915 r270 bottom
R25 "RES_R0402_DISCRETE_1K" R0402#2 440,915 r270 bottom
R26 "RES_R0402_DISCRETE_100K" R0402#2 2015,2809.37 r0 bottom
R27 "RES_R0402_DISCRETE_0R" R0402#2 2015,2689.37 r0 bottom
R28 "RES_R0402_DISCRETE_10K" R0402#2 440,995 r90 bottom
R29 "RES_R0402_DISCRETE_100K" R0402#2 2095,2849.37 r0 bottom
R30 "RES_R0603_DISCRETE_0R" R0603#1 650,1410 r90 bottom
R31 "RES_R0402_DISCRETE_100K" R0402#2 2015,2969.37 r0 bottom
R32 "RES_R0603_DISCRETE_NC" R0603#1 595,1410 r90 bottom
R33 "RES_R0402_DISCRETE_0R" R0402#2 1820,2579.37 r270 bottom
R34 "RES_R0402_DISCRETE_0R" R0402#2 1740,2579.37 r270 bottom
R35 "RES_R0402_DISCRETE_20K" R0402#2 390,1722 r0 bottom
R36 "RES_R0402_DISCRETE_0R" R0402#2 2015,2929.37 r0 bottom
R37 "RES_R0402_DISCRETE_20K" R0402#2 510,1785 r270 bottom
R38 "RES_R0402_DISCRETE_0R" R0402#2 1780,2579.37 r270 bottom
R39 "RES_R0402_DISCRETE_1K" R0402#2 744,1765 r270 bottom
R40 "RES_R0402_DISCRETE_10K" R0402#2 704,1765 r90 bottom
R41 "RES_R0402_DISCRETE_0R" R0402#2 3450,2699.37 r270 bottom
R42 "RES_R0402_DISCRETE_0R" R0402#2 3490,2699.37 r270 bottom
R43 "RES_R0402_DISCRETE_22R" R0402#2 2202.61,2729.37 r270 bottom
R44 "RES_R0402_DISCRETE_22R" R0402#2 2247.61,2729.37 r270 bottom
R45 "RES_R0402_DISCRETE_22R" R0402#2 2292.61,2729.37 r270 bottom
R46 "RES_R0402_DISCRETE_22R" R0402#2 2427.61,2729.37 r270 bottom
R47 "RES_R0402_DISCRETE_22R" R0402#2 2472.61,2729.37 r270 bottom
R48 "RES_R0402_DISCRETE_22R" R0402#2 2517.61,2729.37 r270 bottom
R49 "RES_R0402_DISCRETE_0R" R0402#2 2562.61,2729.37 r270 bottom
R50 "RES_R0402_DISCRETE_510R" R0402#2 1515,2505 r270 bottom
R51 "RES_R0805_DISCRETE_1M" R0805 895,2500 r90 bottom
R52 "RES_R0402_DISCRETE_2.2R" R0402#2 2845,2324.37 r270 bottom
R53 "RES_R0402_DISCRETE_2.2R" R0402#2 2900,2324.37 r270 bottom
R54 "RES_R0402_DISCRETE_0R" R0402#2 2945,2324.37 r270 bottom
R55 "RES_R0402_DISCRETE_0R" R0402#2 3000,2324.37 r270 bottom
R56 "RES_R0402_DISCRETE_1K" R0402#2 2840,2934.37 r90 bottom
R57 "RES_R0402_DISCRETE_3.4K" R0402#2 2795,2934.37 r90 bottom
R58 "RES_R0402_DISCRETE_10K" R0402#2 3145,2929.37 r90 bottom
R59 "RES_R0402_DISCRETE_15K" R0402#2 3185,2929.37 r270 bottom
R60 "RES_R0402_DISCRETE_0R" R0402#2 3458.11,1925 r90 top
R61 "RES_R0402_DISCRETE_100K" R0402#2 3498.11,2300 r90 top
R62 "RES_R0402_DISCRETE_100K" R0402#2 3458.11,2300 r90 top
R63 "RES_R0402_DISCRETE_100K" R0402#2 3578.11,2300 r90 top
R64 "RES_R0402_DISCRETE_2.2R" R0402#2 3618.11,2300 r90 top
R65 "RES_R0402_DISCRETE_2.2R" R0402#2 3658.11,2300 r90 top
R66 "RES_R0402_DISCRETE_2.7K" R0402#2 3698.11,2300 r90 top
R67 "RES_R0402_DISCRETE_1K" R0402#2 4343.11,1720 r270 top
R68 "RES_R0402_DISCRETE_3.4K" R0402#2 4443.11,1720 r90 top
R69 "RES_R0402_DISCRETE_100R" R0402#2 280,2769.37 r180 top
R70 "RES_R0402_DISCRETE_100R" R0402#2 115,2769.37 r180 top
R71 "RES_R0402_DISCRETE_100R" R0402#2 3598.11,959 r90 bottom
R72 "RES_R0402_DISCRETE_100R" R0402#2 3713.11,959 r90 bottom
R73 "RES_R0402_DISCRETE_4.7K" R0402#1 1245,875 r0 bottom
R74 "RES_R0402_DISCRETE_NC" R0402#2 1245,590 r180 top
R75 "RES_R0402_DISCRETE_NC" R0402#2 1245,630 r180 top
R76 "RES_R0402_DISCRETE_10K" R0402#2 1245,710 r180 top
R77 "RES_R0402_DISCRETE_10K" R0402#2 1245,670 r180 top
R78 "RES_R0603_DISCRETE_0R" R0603#1 840,555 r270 bottom
R79 "RES_R0603_DISCRETE_0R" R0603#1 1250,555 r270 bottom
R80 "RES_R0402_DISCRETE_10K" R0402#1 345,490 r0 bottom
R81 "RES_R0402_DISCRETE_NC" R0402#2 3170,430 r270 bottom
R82 "RES_R0402_DISCRETE_10K" R0402#1 345,530 r0 bottom
R83 "RES_R0402_DISCRETE_NC" R0402#2 675,930 r0 top
R84 "RES_R0603_DISCRETE_0R" R0603#1 1060,555 r270 bottom
R85 "RES_R0402_DISCRETE_0R" R0402#2 755,930 r0 top
R86 "RES_R0201_DISCRETE_0R" R0201 1169.33,980 r270 top
R87 "RES_R0201_DISCRETE_NC" R0201 1169.33,1045 r90 top
R88 "RES_R0201_DISCRETE_NC" R0201 1129.96,1045 r90 top
R89 "RES_R0201_DISCRETE_0R" R0201 1129.96,980 r270 top
R90 "RES_R0201_DISCRETE_0R" R0201 1090.59,980 r270 top
R91 "RES_R0201_DISCRETE_NC" R0201 1090.59,1045 r90 top
R92 "RES_R0201_DISCRETE_NC" R0201 1051.22,1045 r90 top
R93 "RES_R0201_DISCRETE_0R" R0201 1051.22,980 r270 top
R94 "RES_R0201_DISCRETE_0R" R0201 933.11,980 r270 top
R95 "RES_R0201_DISCRETE_NC" R0201 933.11,1045 r90 top
R96 "RES_R0201_DISCRETE_NC" R0201 893.74,1045 r90 top
R97 "RES_R0201_DISCRETE_0R" R0201 893.74,980 r270 top
R98 "RES_R0402_DISCRETE_100R" R0402#2 3125,165 r90 bottom
R99 "RES_R0201_DISCRETE_0R" R0201 854.37,980 r270 top
R100 "RES_R0201_DISCRETE_NC" R0201 854.37,1045 r90 top
R101 "RES_R0201_DISCRETE_NC" R0201 815,1045 r90 top
R102 "RES_R0201_DISCRETE_0R" R0201 815,980 r270 top
R103 "RES_R0402_DISCRETE_100R" R0402#2 3050,165 r90 bottom
R104 "RES_R0201_DISCRETE_0R" R0201 1011.85,980 r270 top
R105 "RES_R0201_DISCRETE_NC" R0201 1011.85,1045 r90 top
R106 "RES_R0201_DISCRETE_NC" R0201 972.48,1045 r90 top
R107 "RES_R0201_DISCRETE_0R" R0201 972.48,980 r270 top
R108 "RES_R0402_DISCRETE_100R" R0402#2 2890,165 r90 bottom
R109 "RES_R0402_DISCRETE_4.7K" R0402#2 4315,280 r90 bottom
R110 "RES_R0402_DISCRETE_120R" R0402#2 4315,200 r90 bottom
R111 "RES_R0603_DISCRETE_10K" R0603#2 3910,230 r0 bottom
R112 "RES_R0402_DISCRETE_4.7K" R0402#2 4315,120 r270 bottom
R113 "RES_R0402_DISCRETE_NC" R0402#2 3865.91,1473 r90 top
R114 "RES_R0402_DISCRETE_NC" R0402#2 3761.91,1473 r90 top
R115 "RES_R0402_DISCRETE_NC" R0402#1 3910,180 r0 bottom
R116 "RES_R0402_DISCRETE_NC" R0402#2 3560.91,1473 r90 top
R117 "RES_R0402_DISCRETE_NC" R0402#1 3910,345 r0 bottom
R118 "RES_R0402_DISCRETE_NC" R0402#2 3660.91,1473 r90 top
R119 "RES_R0402_DISCRETE_4.7K" R0402#2 3741,280 r90 bottom
R120 "RES_R0402_DISCRETE_120R" R0402#2 3741,200 r90 bottom
R121 "RES_R0603_DISCRETE_10K" R0603#2 3346,230 r0 bottom
R122 "RES_R0402_DISCRETE_4.7K" R0402#2 3741,120 r270 bottom
R123 "RES_R0402_DISCRETE_NC" R0402#2 4404.11,1473 r90 top
R124 "RES_R0402_DISCRETE_NC" R0402#2 4304.11,1473 r90 top
R125 "RES_R0402_DISCRETE_NC" R0402#1 3346,180 r0 bottom
R126 "RES_R0402_DISCRETE_NC" R0402#2 4104.11,1473 r90 top
R127 "RES_R0402_DISCRETE_NC" R0402#1 3346,345 r0 bottom
R128 "RES_R0402_DISCRETE_NC" R0402#2 4204.11,1473 r90 top
R129 "RES_R0402_DISCRETE_NC" R0402#2 4623.11,2130 r0 top
R130 "RES_R0402_DISCRETE_10K" R0402#2 4378.11,2249.37 r270 bottom
R131 "RES_R0402_DISCRETE_10K" R0402#2 4418.11,2249.37 r270 bottom
R132 "RES_R0603_DISCRETE_0R" R0603#2 4813.11,1620 r0 bottom
R133 "RES_R0603_DISCRETE_NC" R0603#2 4813.11,1565 r0 bottom
R134 "RES_R0805_DISCRETE_10R" R0805 4813.11,1885 r0 bottom
R135 "RES_R0402_DISCRETE_22R" R0402#2 4458.11,2249.37 r90 bottom
R136 "RES_R0402_DISCRETE_10K" R0402#2 4813.11,1675 r0 bottom
R137 "RES_R0402_DISCRETE_1K" R0402#2 4968.11,1620 r0 bottom
R138 "RES_R0402_DISCRETE_10K" R0402#1 4968.11,1675 r0 bottom
R139 "RES_R0402_DISCRETE_100R" R0402#2 2410,470 r90 bottom
R140 "RES_R0402_DISCRETE_100R" R0402#2 2330,470 r90 bottom
R141 "RES_R0402_DISCRETE_100R" R0402#2 2250,470 r90 bottom
R142 "RES_R0402_DISCRETE_100R" R0402#2 2170,470 r90 bottom
R143 "RES_R0402_DISCRETE_100R" R0402#2 2095,470 r90 bottom
R144 "RES_R0402_DISCRETE_100R" R0402#2 2015,470 r90 bottom
R145 "RES_R0402_DISCRETE_100R" R0402#2 4033.11,959 r90 bottom
R146 "RES_R0402_DISCRETE_100R" R0402#2 4123.11,959 r90 bottom
R147 "RES_R0402_DISCRETE_100R" R0402#2 4213.11,959 r90 bottom
R148 "RES_R0402_DISCRETE_100R" R0402#2 4303.11,959 r90 bottom
R149 "RES_R0402_DISCRETE_100R" R0402#2 4393.11,959 r90 bottom
R150 "RES_R0402_DISCRETE_0R" R0402#2 4623.11,2170 r180 top
R151 "RES_R0402_DISCRETE_10K" R0402#2 4623.11,1925 r180 top
R152 "RES_R0402_DISCRETE_0R" R0402#2 4623.11,2210 r180 top
R153 "RES_R0402_DISCRETE_0R" R0402#2 4623.11,2250 r180 top
R154 "RES_R0402_DISCRETE_0R" R0402#2 4623.11,2290 r180 top
R155 "RES_R0402_DISCRETE_0R" R0402#2 4623.11,1965 r0 top
R156 "RES_R0402_DISCRETE_0R" R0402#2 4313.11,2495 r270 top
R157 "RES_R0402_DISCRETE_22R" R0402#2 4283.11,1615 r270 top
R158 "RES_R0402_DISCRETE_0R" R0402#2 4273.11,2495 r270 top
R159 "RES_R0402_DISCRETE_22R" R0402#2 4283.11,1720 r270 top
R160 "RES_R0402_DISCRETE_22R" R0402#2 4233.11,1615 r270 top
R161 "RES_R0402_DISCRETE_22R" R0402#2 4233.11,1720 r270 top
R162 "RES_R0402_DISCRETE_22R" R0402#2 4128.11,1720 r270 top
R163 "RES_R0402_DISCRETE_NC" R0402#2 4168.11,1720 r90 top
R164 "RES_R0402_DISCRETE_10K" R0402#2 3923.11,2280 r0 top
R165 "RES_R0402_DISCRETE_0R" R0402#2 3923.11,2320 r0 top
R166 "RES_R0402_DISCRETE_0R" R0402#2 3923.11,2240 r0 top
R167 "RES_R0603_DISCRETE_0R" R0603#1 3923.11,2145 r270 top
R168 "RES_R0402_DISCRETE_0R" R0402#1 345,1150 r0 bottom
R169 "RES_R0402_DISCRETE_0R" R0402#1 345,2490 r0 bottom
R170 "RES_R0402_DISCRETE_0R" R0402#1 345,2030 r0 bottom
R171 "RES_R0402_DISCRETE_49.9K" R0402#1 3315,1745 r0 bottom
R172 "RES_R0402_DISCRETE_0R" R0402#1 345,705 r0 bottom
R173 "RES_R0402_DISCRETE_10K" R0402#2 3315,1785 r0 bottom
R174 "RES_R0402_DISCRETE_2.2K" R0402#2 2730,2158.74 r90 bottom
R175 "RES_R0402_DISCRETE_2.2K" R0402#2 2690,2158.74 r90 bottom
R176 "RES_R0402_DISCRETE_NC" R0402#2 3130,430 r270 bottom
R177 "RES_R0402_DISCRETE_NC" R0402#2 2950,430 r270 bottom
R178 "RES_R0402_DISCRETE_0R" R0402#2 3210,430 r270 bottom
R179 "RES_R0402_DISCRETE_1K" R0402#2 460,560 r0 bottom
R180 "RES_R0402_DISCRETE_3.4K" R0402#1 562,550 r0 bottom
R181 "RES_R0402_DISCRETE_3.4K" R0402#1 562.5,670 r0 bottom
R182 "RES_R0402_DISCRETE_NC" R0402#2 2990,430 r270 bottom
R183 "RES_R0402_DISCRETE_0R" R0402#2 3030,430 r270 bottom
R184 "RES_R0402_DISCRETE_NC" R0402#2 2805,430 r270 bottom
R185 "RES_R0402_DISCRETE_0R" R0402#2 2845,430 r270 bottom
R186 "RES_R0402_DISCRETE_NC" R0402#2 2665,430 r270 bottom
R187 "RES_R0402_DISCRETE_0R" R0402#2 2705,430 r270 bottom
R188 "RES_R0402_DISCRETE_10K" R0402#2 725,1285 r0 top
R189 "RES_R0402_DISCRETE_2.2K" R0402#2 2650,2158.74 r90 bottom
R190 "RES_R0402_DISCRETE_2.2K" R0402#2 2610,2158.74 r90 bottom
R191 "RES_R0402_DISCRETE_2.2K" R0402#2 1410,676 r0 bottom
R192 "RES_R0402_DISCRETE_2.2K" R0402#2 1410,636 r0 bottom
R193 "RES_R0402_DISCRETE_100R" R0402#2 3225,2930 r270 bottom
R213 "RES_R0402_DISCRETE_NC" R0402#2 800,1410 r90 top
R214 "RES_R0402_DISCRETE_NC" R0402#2 795,1605 r90 top
R215 "RES_R0402_DISCRETE_10K" R0402#2 800,1500 r270 top
R216 "RES_R0402_DISCRETE_10K" R0402#2 795,1695 r270 top
R237 "RES_R0402_DISCRETE_120R" R0402#2 5030,755 r90 bottom
R238 "RES_R0402_DISCRETE_NC" R0402#2 5030,675 r270 bottom
R239 "RES_R0402_DISCRETE_22R" R0402#1 4805,575 r0 bottom
R240 "RES_R0402_DISCRETE_22R" R0402#1 4805,935 r0 bottom
R241 "RES_R0402_DISCRETE_NC" R0402#1 4890,575 r0 bottom
R242 "RES_R0402_DISCRETE_0R" R0402#2 4970,575 r0 bottom
R243 "RES_R0402_DISCRETE_NC" R0402#1 4890,935 r0 bottom
R244 "RES_R0402_DISCRETE_0R" R0402#2 4970,935 r0 bottom
R245 "RES_R0402_DISCRETE_22R" R0402#2 4655,1160 r0 bottom
R246 "RES_R0402_DISCRETE_22R" R0402#2 4655,1200 r0 bottom
R247 "RES_R0402_DISCRETE_120R" R0402#2 5030,1180 r90 bottom
R248 "RES_R0402_DISCRETE_NC" R0402#1 4655,1120 r0 bottom
R249 "RES_R0402_DISCRETE_0R" R0402#2 5030,595 r90 bottom
R250 "RES_R0402_DISCRETE_0R" R0402#2 5030,915 r270 bottom
R251 "RES_R0402_DISCRETE_NC" R0402#2 5030,835 r90 bottom
R252 "RES_R0402_DISCRETE_NC" R0402#2 5030,1100 r270 bottom
R253 "RES_R0402_DISCRETE_0R" R0402#2 4655,1080 r0 bottom
R254 "RES_R0402_DISCRETE_0R" R0402#2 5030,1020 r90 bottom
R255 "RES_R0402_DISCRETE_0R" R0402#2 4655,1280 r0 bottom
R256 "RES_R0402_DISCRETE_0R" R0402#2 5030,1340 r270 bottom
R257 "RES_R0402_DISCRETE_NC" R0402#1 4655,1240 r0 bottom
R258 "RES_R0402_DISCRETE_NC" R0402#2 5030,1260 r90 bottom
R259 "RES_R0402_DISCRETE_NC" R0402#2 4885,350 r90 top
R260 "RES_R0402_DISCRETE_0R" R0402#2 4845,350 r90 top
R261 "RES_R0402_DISCRETE_22R" R0402#2 1255,1595 r270 top
SS1 "SPACER_PTH_M3_IC_PTH_M3" PTH_M3 531.5,118.11 r0 top
SS2 "SPACER_PTH_M3_IC_PTH_M3" PTH_M3 4862.2,118.11 r0 top
SS3 "SPACER_PTH_M3_IC_PTH_M3" PTH_M3 4862.21,2401.57 r0 top
SS4 "SPACER_PTH_M3_IC_PTH_M3" PTH_M3 531.5,2401.57 r0 top
SW1 "SW_PB_ESW_SW4-4R20X3R25-SM_IC_S" SW4-4R20X3R25-SM 1000,1595 r180 top
T1 "IND-4P_L4_2012_T_WBA0805D801PT-" L4_2012_T 1135,2135 r90 bottom
T2 "IND-4P_L4_3216_T_WBA3416L600T-D" L4_3216_T 1135,2255 r0 bottom
T3 "IND-4P_L4_2012_T_WBA0805D801PT-" L4_2012_T 1310,2135 r90 bottom
T4 "IND-4P_L4_3216_T_WBA3416L600T-D" L4_3216_T 1310,2255 r0 bottom
T5 "IND-4P_L4_2012_T_WBA0805D801PT-" L4_2012_T 1485,2135 r90 bottom
T6 "IND-4P_L4_3216_T_WBA3416L600T-D" L4_3216_T 1485,2255 r0 bottom
T7 "IND-4P_L4_2012_T_WBA0805D801PT-" L4_2012_T 1660,2135 r90 bottom
T8 "IND-4P_L4_3216_T_WBA3416L600T-D" L4_3216_T 1660,2255 r0 bottom
U1 "TP6327GS6_SOT23_6_ASP9135ZC-R" SOT23_6 508,2200 r90 top
U2 "TP6327GS6_SOT23_6_ASP9135ZC-R" SOT23_6 1185,2200 r90 top
U3 "TP6327GS6_SOT23_6_ASP9135ZC-R" SOT23_6 955,2200 r90 top
U4 "TP6327GS6_SOT23_6_ASP9135ZC-R" SOT23_6 725,2200 r90 top
U5 "NS4110B_SOP-8-EP-2R5X3R4_NS4110" SOP-8-EP-2R5X3R4 520,1010 r0 top
U6 "NS4110B_SOP-8-EP-2R5X3R4_NS4110" SOP-8-EP-2R5X3R4 520,1575 r180 top
U7 "MT9700_SOT23-5_MT9700" SOT23-5#1 2975,2929.37 r0 bottom
U8 "FE1.1S-BQFN24B_QFN24_CH334F" QFN24 3618.11,2102.56 r90 top
U9 "MT9700_SOT23-5_MT9700" SOT23-5#2 4398.11,1610 r90 top
U10 "GM8775C_QFN45-0R50-7R10X7R10EP5" QFN45-0R50-7R10X7R10EP5R40X5R40 999.9,715 r90 top
U11 "74LVC1G125_SOT-353_74LVC1G125GW" SOT-353 280,2664.37 r180 top
U12 "74LVC1G125_SOT-353_74LVC1G125GW" SOT-353 115,2664.37 r180 top
U13 "MT9700_SOT23-5_MT9700" SOT23-5#2 520,485 r90 top
U14 "MT9700_SOT23-5_MT9700" SOT23-5#2 520,630 r90 top
U15 "HYM8563S_MSOP-8_BM8563EMA" MSOP-8 4393.11,2129.37 r90 bottom
U16 "AP6212_AP6212_BL-M8189FS6" AP6212 4278.11,2102.56 r270 top
U17 "XL9535_TSSOP24-0R65-7R80X4R40_X" TSSOP24-0R65-7R80X4R40 1000,1315 r180 top
U18 "TJA1057GT3_8P_SOP8_IC_NC" SOP8 4850,755 r90 bottom
U19 "TJA1057GT3_8P_SOP8_IC_NC" SOP8 4850,1180 r90 bottom
U21 "74LVC1T45_X2-DFN1410-6_74LVC1T4" X2-DFN1410-6 725,1455 r0 top
U22 "74LVC1T45_X2-DFN1410-6_74LVC1T4" X2-DFN1410-6 725,1650 r0 top
U23 "MAX3232CSE_SOIC16_SIT3232EESE" SOIC16 3741.11,1220 r90 top
U24 "SIT3088E-8P_SOP8_IC_SIT3088EESA" SOP8 4130,200 r90 bottom
U25 "MAX3232CSE_SOIC16_SIT3232EESE" SOIC16 4278.11,1220 r90 top
U26 "SIT3088E-8P_SOP8_IC_SIT3088EESA" SOP8 3561,200 r90 bottom
U27 "RT9193-XXGB_SOT23-5_RT9193-18GB" SOT23-5#2 520,770 r90 top
Y1 "CRYSTAL_4P_3225_IC_12MHZ" 3225 3618.11,1820 r0 top
Y2 "OSCILLATOR_4P_3225_NC" 3225 712,1013 r180 top
Y3 "CRYSTAL_2P_3215_32.768KHZ" 3215 4163.11,2104.37 r90 bottom
Y4 "OSCILLATOR_4P_3225_32.768KHZ" 3225 4123.11,1615 r0 top

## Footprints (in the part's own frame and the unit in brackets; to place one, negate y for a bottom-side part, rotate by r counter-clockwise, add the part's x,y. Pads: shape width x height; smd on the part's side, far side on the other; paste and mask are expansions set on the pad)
3215 [mm] "3215"
  rect 1.4x1.2 smd: 1(-1.001,0) 2(1.001,0)
  silkscreen extent -1.9,-0.9 1.9,0.9
3225 [mm] "3225"
  rect 1.3x1 smd: 1(-1.15,-0.75) 2(1.15,-0.75) 3(1.15,0.75) 4(-1.15,0.75)
  silkscreen extent -2.59,-1.2 0.3,1.2, body extent -1.9,-1.4 1.9,1.4, height 3.81
AP6212 [mm] "AP6212"
  rect 1.5x0.6 smd: 1(-6,4.5) 2(-6,3.6) 3(-6,2.7) 4(-6,1.8) 5(-6,0.9) 6(-6,0) 7(-6,-0.9) 8(-6,-1.8) 9(-6,-2.7) 10(-6,-3.6) 11(-6,-4.5) 23(6,-4.5) 24(6,-3.6) 25(6,-2.7) 26(6,-1.8) 27(6,-0.9) 28(6,0) 29(6,0.9) 30(6,1.8) 31(6,2.7) 32(6,3.6) 33(6,4.5)
  rect 0.6x1.5 smd: 12(-4.5,-6) 13(-3.6,-6) 14(-2.7,-6) 15(-1.8,-6) 16(-0.9,-6) 17(0,-6) 18(0.9,-6) 19(1.8,-6) 20(2.7,-6) 21(3.6,-6) 22(4.5,-6) 34(4.5,6) 35(3.6,6) 36(2.7,6) 37(1.8,6) 38(0.9,6) 39(0,6) 40(-0.9,6) 41(-1.8,6) 42(-2.7,6) 43(-3.6,6) 44(-4.5,6)
  round 0.6 smd: 45(-2.7,3.6) 46(-0.9,3.6) 47(0.9,3.6)
  silkscreen extent -6.12,-6 6,6.12, body extent -6.75,-6.75 6.75,6.75, height 3.81
AV7_6X14R50_TM [mm] "AV7_6X14R50_TM"
  oval 1.2x2 hole 1.5 slot 0.75 at 0 deg: 1(-2.3,3.35) 2(-2.3,0.25) 3(-2.3,-2.55) 4(2.3,-2.95) 6(2.3,2.15) 7(2.3,-0.65) 8(-2.3,-4.85)
  round 1.2 hole 1.2 unplated: ""(0,-3.35) ""(0,3.65)
  silkscreen extent -3.05,-7.25 3.05,7.25, body extent -3,-7.25 3,7.25, height 3.81
C0402#1 [mil] "C0402"
  rect 23.6x23.6 smd: 1(-19.68,0) 2(19.68,0)
  silkscreen extent -37,-17 37,17, body extent -37,-17 37,17, height 150
C0402#2 [mil] "C0402"
  rect 23.6x23.6 smd: 1(19.68,0) 2(-19.68,0)
  silkscreen extent -37,-17 37,17, body extent -37,-17 37,17, height 150
C0603#1 [mil] "C0603"
  rect 31.5x31.5 smd: 1(-31.5,0) 2(31.5,0)
  silkscreen extent -55,-25 55,25, body extent -48,-16 48,16, height 150
C0603#2 [mil] "C0603"
  rect 31.5x31.5 smd: 1(31.5,0) 2(-31.5,0)
  silkscreen extent -55,-25 55,25, body extent -48,-16 48,16, height 150
C0805 [mm] "C0805"
  rect 1.16x1.47 smd: 1(-0.89,0) 2(0.89,0)
  silkscreen extent -1.77,-1.03 1.77,1.03
C1206 [mil] "C1206"
  rect 47.24x74.8 smd: 1(-62.99,0) 2(62.99,0)
  silkscreen extent -94,-47 94,47
DC_IN_TH_3P_10R1X11R6 [mil] "DC_IN_TH_3P_10R1X11R6"
  oval 94.5x39.4 hole 70.9 slot 15.7 at 90 deg: 1(-111.25,-194.9) 5(-111.25,190.9)
  oval 102.4x43.3 hole 66.9 slot 19.7 at 90 deg: 2(174.25,-51.2) 3(174.25,157.4) 4(174.25,-177.2)
  round 78.7 hole 78.7 unplated: ""(-69.85,-51.2)
  silkscreen extent -232,-201 226,197, body extent -237,-228 237,228, height 150
ES0402 [mil] "ES0402"
  rect 23.6x23.6 smd: 1(-19.68,0) 2(19.68,0)
  silkscreen extent -37,-17 37,17, body extent -37,-17 37,17, height 150
F1812 [mm] "F1812"
  rect 1.78x3.3 smd: 1(-2.305,0) 2(2.305,0)
  silkscreen extent -3.4,-1.9 3.4,1.9, body extent -3.4,-1.9 3.4,1.9, height 3.81
FPC-30P-0P5 [mm] "FPC-30P-0P5"
  rect 0.3x1.3 smd: 1(7.25,-2.733) 2(6.75,-2.733) 3(6.25,-2.733) 4(5.75,-2.733) 5(5.25,-2.733) 6(4.75,-2.733) 7(4.25,-2.733) 8(3.75,-2.733) 9(3.25,-2.733) 10(2.75,-2.733) 11(2.25,-2.733) 12(1.75,-2.733) 13(1.25,-2.733) 14(0.75,-2.733) 15(0.25,-2.733) 16(-0.25,-2.733) 17(-0.75,-2.733) 18(-1.25,-2.733) 19(-1.75,-2.733) 20(-2.25,-2.733) 21(-2.75,-2.733) 22(-3.25,-2.733) 23(-3.75,-2.733) 24(-4.25,-2.733) 25(-4.75,-2.733) 26(-5.25,-2.733) 27(-5.75,-2.733) 28(-6.25,-2.733) 29(-6.75,-2.733) 30(-7.25,-2.733)
  rect 1.6x2 smd: 31(-9.4,-0.032) 32(9.4,-0.032)
  silkscreen extent -10.05,-4.14 10.05,3.27, body extent -10.05,-3.35 10.05,3.35, height 3.81
FPC_24P_0P5 [mm] "FPC_24P_0P5"
  rect 0.3x1.3 smd: 1(-5.75,-2.701) 2(-5.25,-2.701) 3(-4.75,-2.701) 4(-4.25,-2.701) 5(-3.75,-2.701) 6(-3.25,-2.701) 7(-2.75,-2.701) 8(-2.25,-2.701) 9(-1.75,-2.701) 10(-1.25,-2.701) 11(-0.75,-2.701) 12(-0.25,-2.701) 13(0.25,-2.701) 14(0.75,-2.701) 15(1.25,-2.701) 16(1.75,-2.701) 17(2.25,-2.701) 18(2.75,-2.701) 19(3.25,-2.701) 20(3.75,-2.701) 21(4.25,-2.701) 22(4.75,-2.701) 23(5.25,-2.701) 24(5.75,-2.701)
  rect 1.6x2 smd: 25(7.45,0.001) 26(-7.45,0.001)
  silkscreen extent -8.1,-3.87 8.1,3.35, body extent -8.1,-3.35 8.1,3.35, height 3.81
GH1P25_TH_2P [mil] "GH1P25_TH_2P"
  rect 35.43x35.43 hole 19.69: 1(-24.65,-33.42)
  round 35.43 hole 19.69: 2(24.57,-33.42)
  silkscreen extent -87,-69 87,69, body extent -92,-74 92,74, height 150
HC-XH-4AWT [mm] "HC-XH-4AWT"
  rect 1.3x4.5 smd: 1(-3.75,3.25) 2(-1.25,3.25) 3(1.25,3.25) 4(3.75,3.25)
  rect 1.8x3.9 smd: 5(-6.95,-3.55) 6(6.95,-3.55)
  silkscreen extent -7.5,-5.45 7.5,6.41, body extent -8,-5.65 8,5.65, height 3.81
HDR1X2-2R54-TM-VM [mm] "HDR1X2-2R54-TM-VM"
  rect 1.6x1.6 hole 1: 1(-1.27,0)
  round 1.6 hole 1: 2(1.27,0)
  silkscreen extent -2.54,-1.25 2.54,1.25, body extent -2.54,-1.25 2.54,1.25, height 3.81
HDR1X3-2R54-TM-VM [mm] "HDR1X3-2R54-TM-VM"
  rect 1.6x1.6 hole 1: 1(-2.535,0)
  round 1.6 hole 1: 2(0.005,0) 3(2.545,0)
  silkscreen extent -3.8,-1.25 3.82,1.25, body extent -3.8,-1.25 3.8,1.25, height 3.81
HDR1X15-2-TM-RM [mm] "HDR1X15-2-TM-RM"
  round 1.4 hole 0.8: 1(-14,-1) 2(-14,1) 3(-12,-1) 4(-12,1) 5(-10,-1) 6(-10,1) 7(-8,-1) 8(-8,1) 9(-6,-1) 10(-6,1) 11(-4,-1) 12(-4,1) 13(-2,-1) 14(-2,1) 15(0,-1) 16(0,1) 17(2,-1) 18(2,1) 19(4,-1) 20(4,1) 21(6,-1) 22(6,1) 23(8,-1) 24(8,1) 25(10,-1) 26(10,1) 27(12,-1) 28(12,1) 29(14,-1) 30(14,1)
  silkscreen extent -15,2 15,7.7, body extent -15,-2 15,2, height 3.81
HDR2X3-2R00-TM-VM [mm] "HDR2X3-2R00-TM-VM"
  rect 1.4x1.4 hole 0.8: 1(-2,-1)
  round 1.4 hole 0.8: 2(-2,1) 3(0,-1) 4(0,1) 5(2,-1) 6(2,1)
  silkscreen extent -3,-2 3,2, body extent -3.1,-2.1 3.1,2.1, height 3.81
